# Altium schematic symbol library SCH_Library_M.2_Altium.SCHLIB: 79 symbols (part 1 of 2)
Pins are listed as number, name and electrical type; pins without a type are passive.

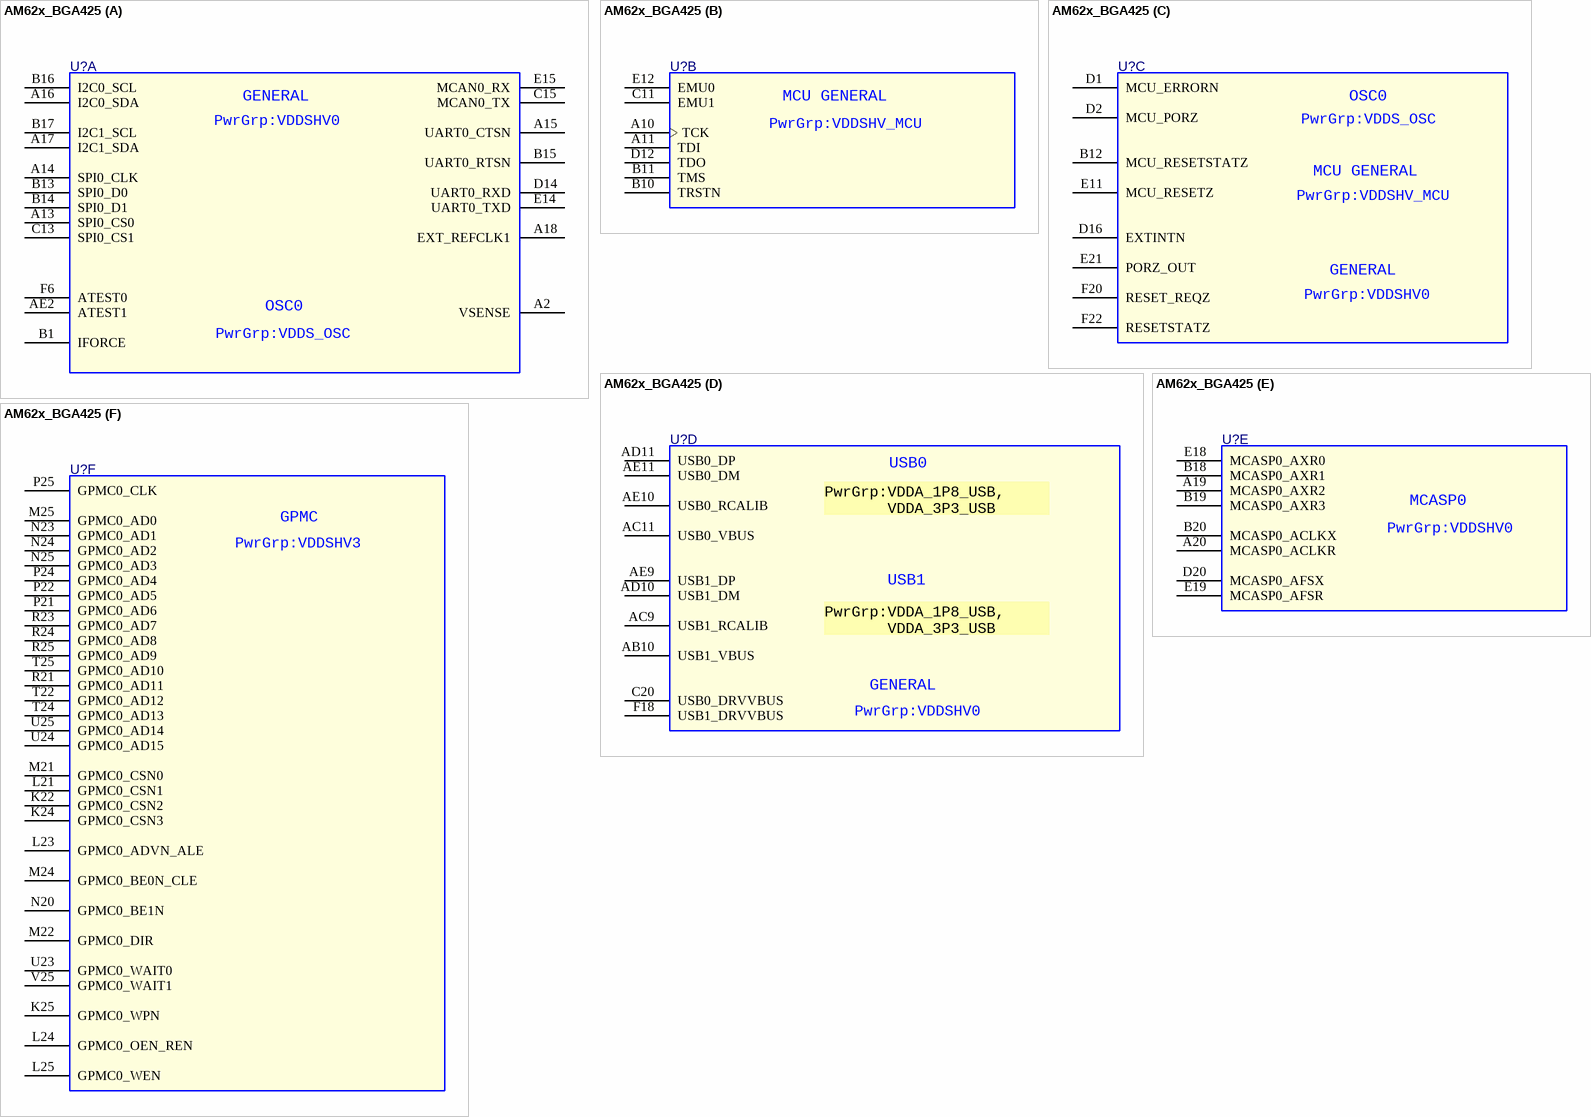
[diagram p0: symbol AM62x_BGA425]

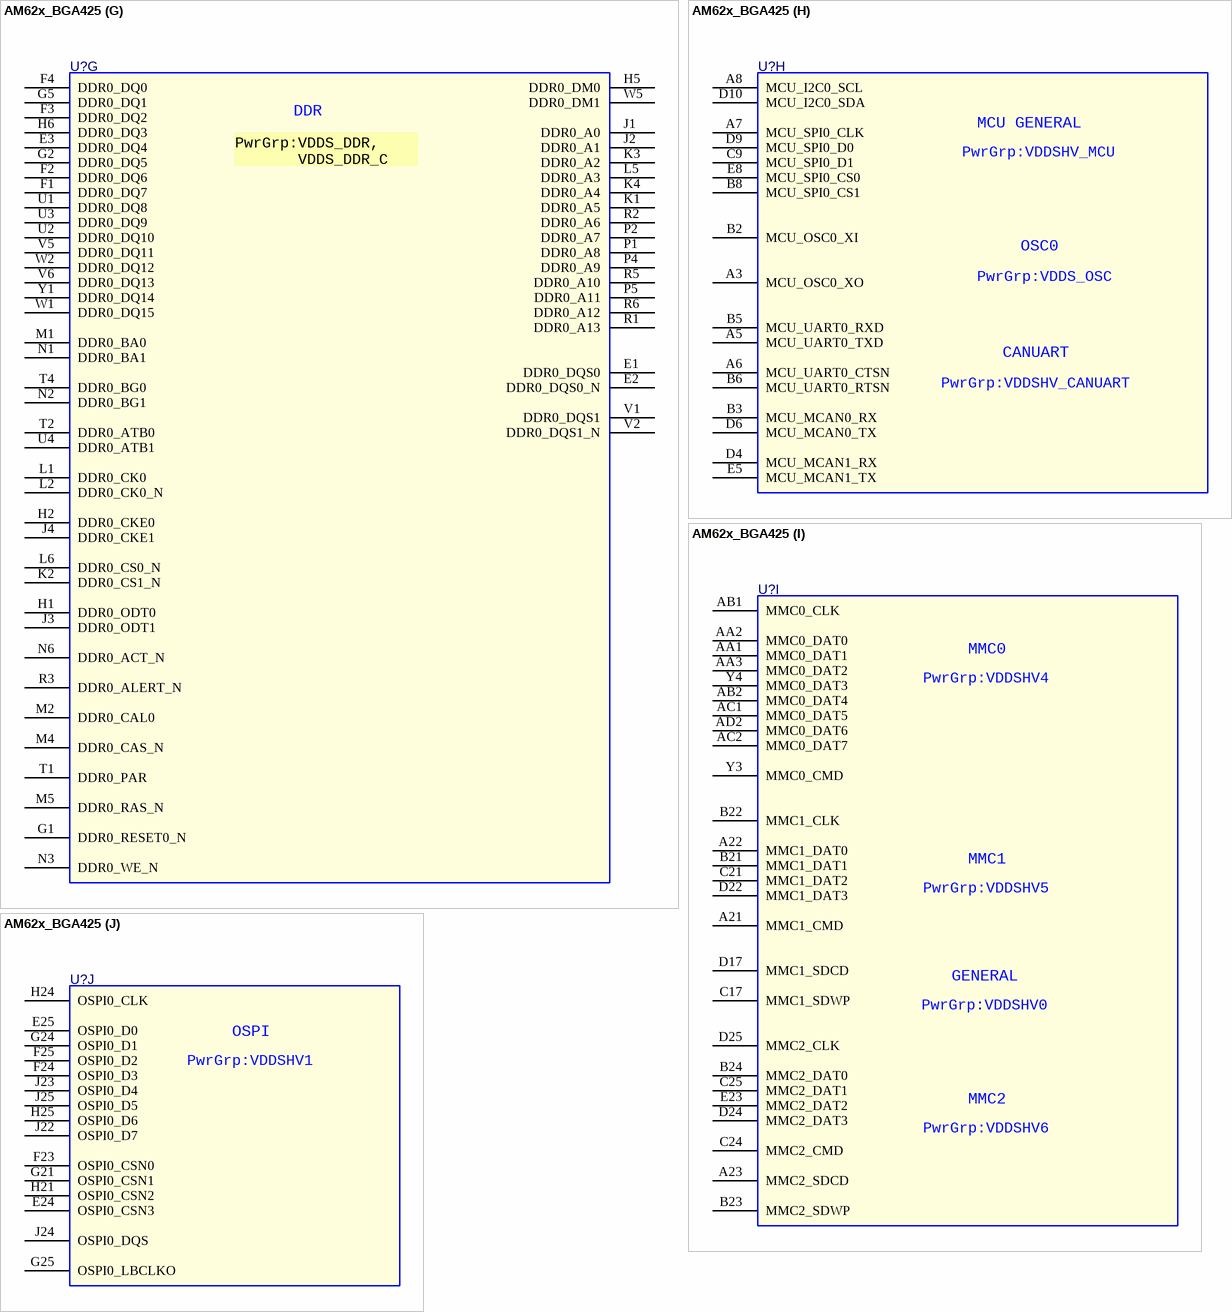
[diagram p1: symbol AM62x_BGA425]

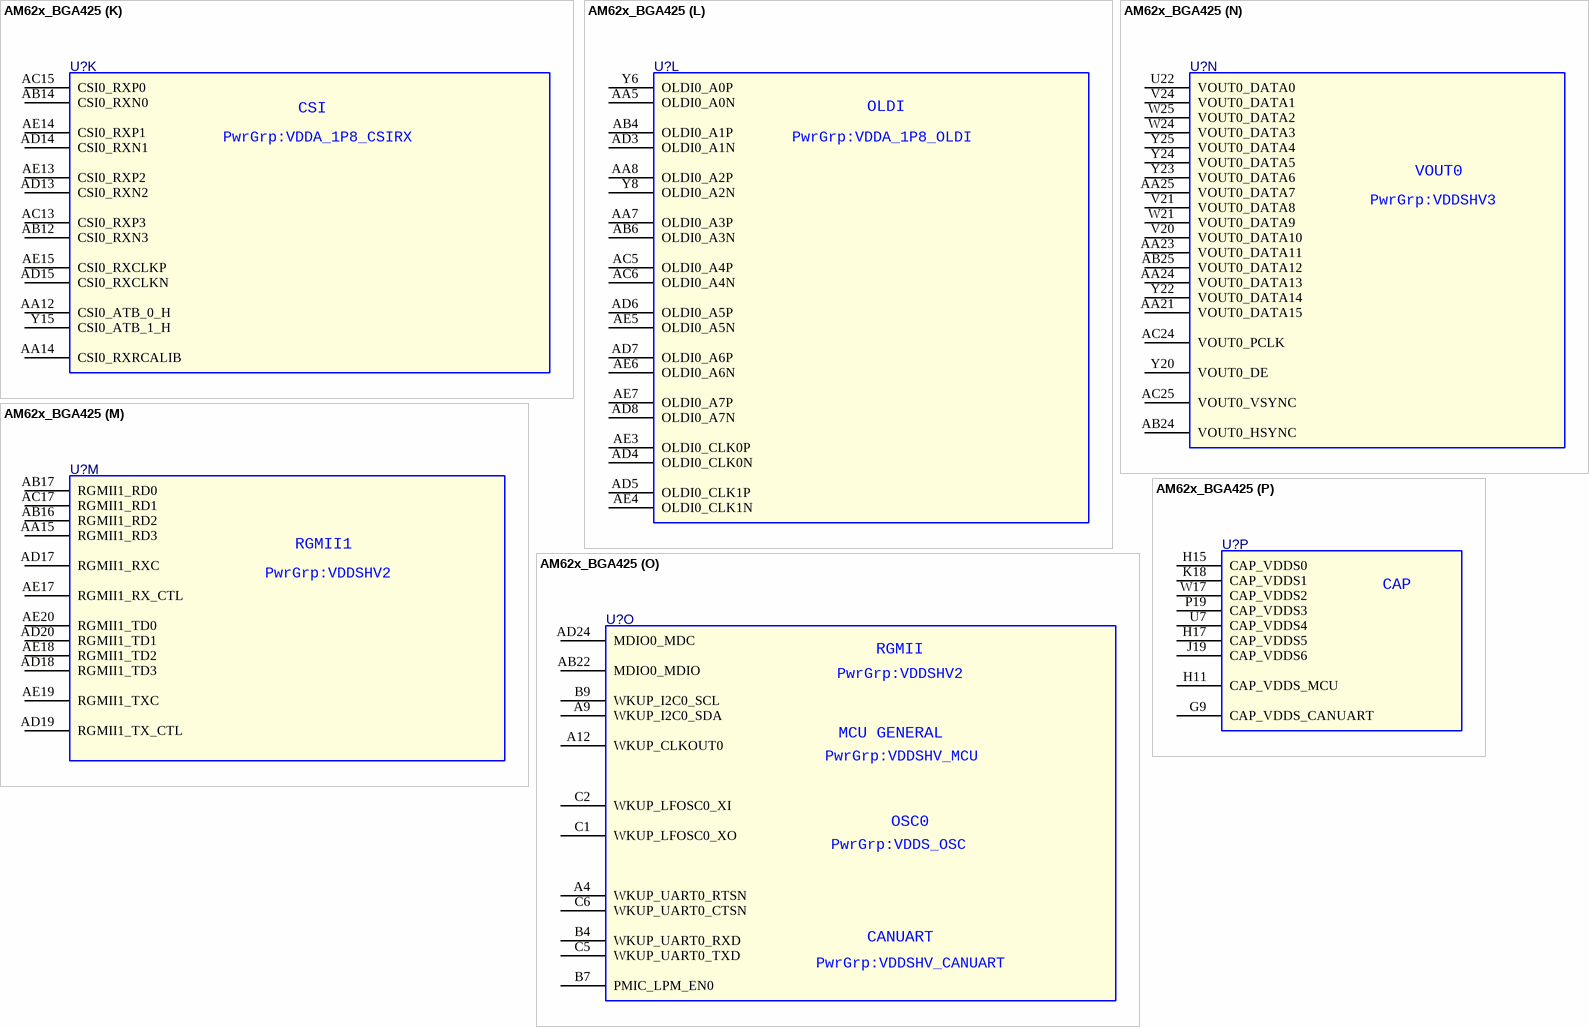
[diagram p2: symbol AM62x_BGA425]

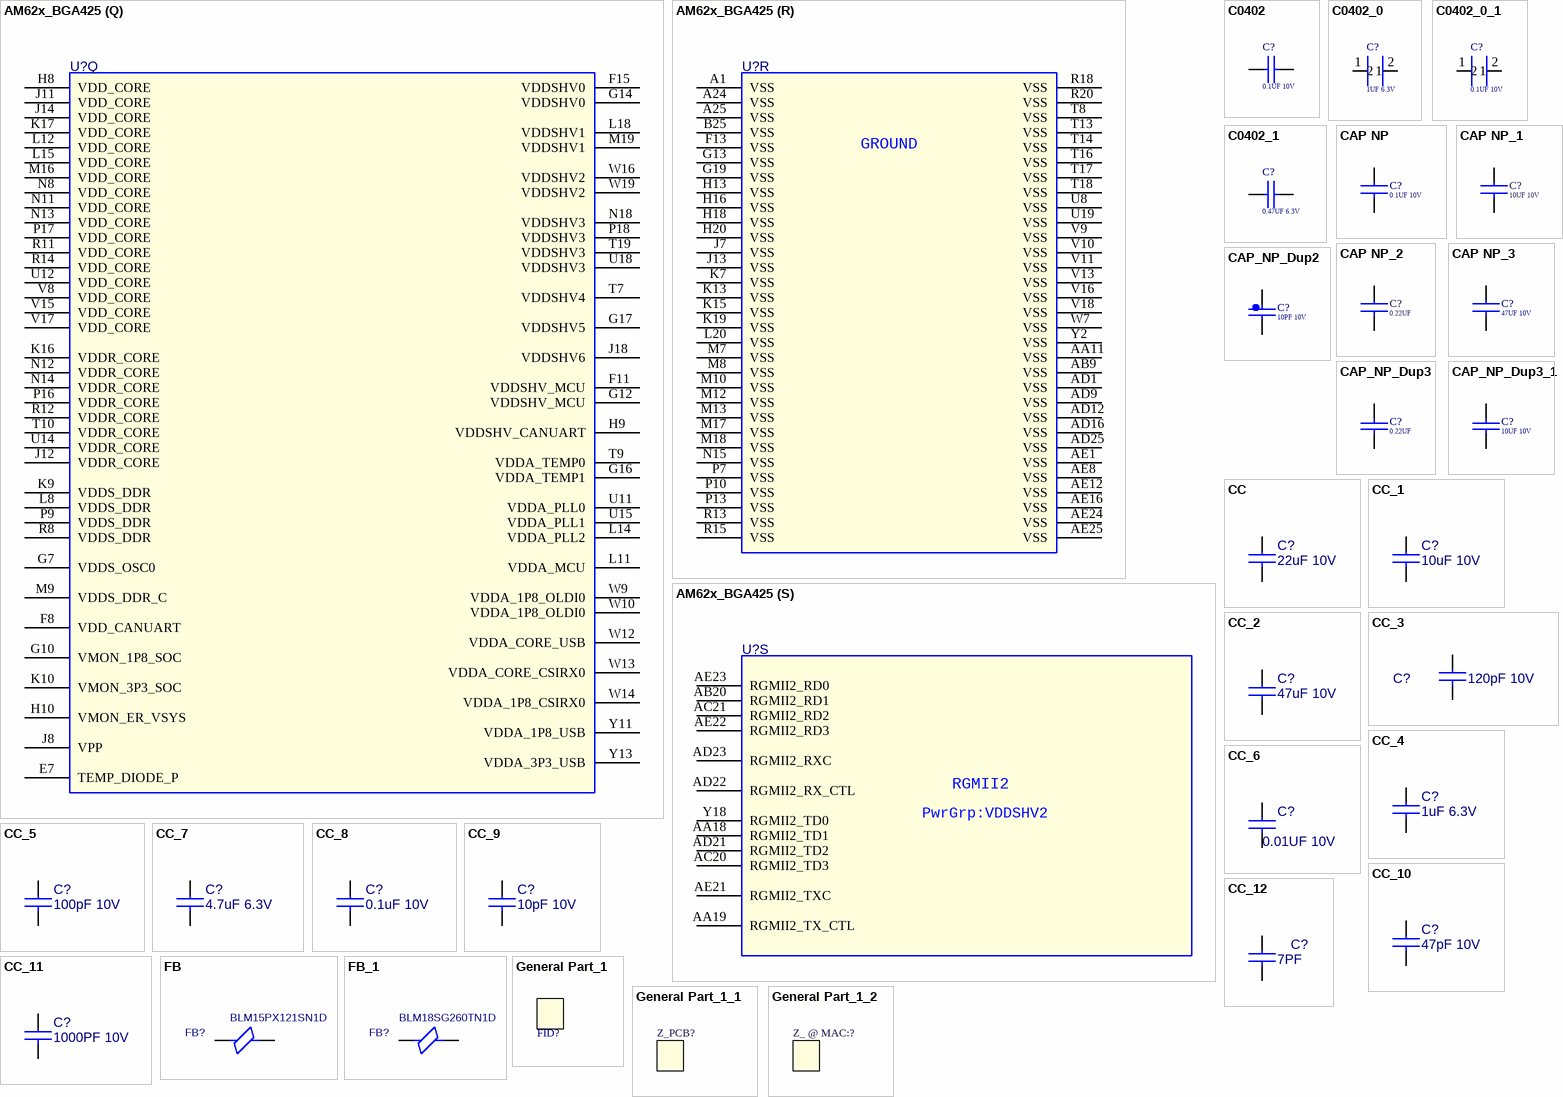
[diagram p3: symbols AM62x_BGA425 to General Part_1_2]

## AM62x_BGA425
designator U?  (value not drawn)
4 Core, 64-Bit 1.4GHz 425-FCC; 01. ASET1 UI1: ------------; 01. Set1/BD#: BD3429; 02. Set1/MF1: Texas Instruments; 03. Set1/PN1: AM6254ATCGHAALW; 09. Z Lay/FP: bga425_0d5_13x13mm
footprint bga425_0d5_13x13mm
part A pins: A2 VSENSE, A13 SPI0_CS0, A14 SPI0_CLK, A15 UART0_CTSN, A16 I2C0_SDA, A17 I2C1_SDA, A18 EXT_REFCLK1, AE2 ATEST1, B1 IFORCE, B13 SPI0_D0, B14 SPI0_D1, B15 UART0_RTSN, B16 I2C0_SCL, B17 I2C1_SCL, C13 SPI0_CS1, C15 MCAN0_TX, D14 UART0_RXD, E14 UART0_TXD, E15 MCAN0_RX, F6 ATEST0
part B pins: A10 TCK, A11 TDI, B10 TRSTN, B11 TMS, C11 EMU1, D12 TDO, E12 EMU0
part C pins: B12 MCU_RESETSTATZ, D1 MCU_ERRORN, D2 MCU_PORZ, D16 EXTINTN, E11 MCU_RESETZ, E21 PORZ_OUT, F20 RESET_REQZ, F22 RESETSTATZ
part D pins: AB10 USB1_VBUS, AC9 USB1_RCALIB, AC11 USB0_VBUS, AD10 USB1_DM, AD11 USB0_DP, AE9 USB1_DP, AE10 USB0_RCALIB, AE11 USB0_DM, C20 USB0_DRVVBUS, F18 USB1_DRVVBUS
part E pins: A19 MCASP0_AXR2, A20 MCASP0_ACLKR, B18 MCASP0_AXR1, B19 MCASP0_AXR3, B20 MCASP0_ACLKX, D20 MCASP0_AFSX, E18 MCASP0_AXR0, E19 MCASP0_AFSR
part F pins: K22 GPMC0_CSN2, K24 GPMC0_CSN3, K25 GPMC0_WPN, L21 GPMC0_CSN1, L23 GPMC0_ADVN_ALE, L24 GPMC0_OEN_REN, L25 GPMC0_WEN, M21 GPMC0_CSN0, M22 GPMC0_DIR, M24 GPMC0_BE0N_CLE, M25 GPMC0_AD0, N20 GPMC0_BE1N, N23 GPMC0_AD1, N24 GPMC0_AD2, N25 GPMC0_AD3, P21 GPMC0_AD6, P22 GPMC0_AD5, P24 GPMC0_AD4, P25 GPMC0_CLK, R21 GPMC0_AD11, R23 GPMC0_AD7, R24 GPMC0_AD8, R25 GPMC0_AD9, T22 GPMC0_AD12, T24 GPMC0_AD13, T25 GPMC0_AD10, U23 GPMC0_WAIT0, U24 GPMC0_AD15, U25 GPMC0_AD14, V25 GPMC0_WAIT1
part G pins: E1 DDR0_DQS0, E2 DDR0_DQS0_N, E3 DDR0_DQ4, F1 DDR0_DQ7, F2 DDR0_DQ6, F3 DDR0_DQ2, F4 DDR0_DQ0, G1 DDR0_RESET0_N, G2 DDR0_DQ5, G5 DDR0_DQ1, H1 DDR0_ODT0, H2 DDR0_CKE0, H5 DDR0_DM0, H6 DDR0_DQ3, J1 DDR0_A0, J2 DDR0_A1, J3 DDR0_ODT1, J4 DDR0_CKE1, K1 DDR0_A5, K2 DDR0_CS1_N, K3 DDR0_A2, K4 DDR0_A4, L1 DDR0_CK0, L2 DDR0_CK0_N, L5 DDR0_A3, L6 DDR0_CS0_N, M1 DDR0_BA0, M2 DDR0_CAL0, M4 DDR0_CAS_N, M5 DDR0_RAS_N, N1 DDR0_BA1, N2 DDR0_BG1, N3 DDR0_WE_N, N6 DDR0_ACT_N, P1 DDR0_A8, P2 DDR0_A7, P4 DDR0_A9, P5 DDR0_A11, R1 DDR0_A13, R2 DDR0_A6, R3 DDR0_ALERT_N, R5 DDR0_A10, R6 DDR0_A12, T1 DDR0_PAR, T2 DDR0_ATB0, T4 DDR0_BG0, U1 DDR0_DQ8, U2 DDR0_DQ10, U3 DDR0_DQ9, U4 DDR0_ATB1, V1 DDR0_DQS1, V2 DDR0_DQS1_N, V5 DDR0_DQ11, V6 DDR0_DQ13, W1 DDR0_DQ15, W2 DDR0_DQ12, W5 DDR0_DM1, Y1 DDR0_DQ14
part H pins: A3 MCU_OSC0_XO, A5 MCU_UART0_TXD, A6 MCU_UART0_CTSN, A7 MCU_SPI0_CLK, A8 MCU_I2C0_SCL, B2 MCU_OSC0_XI, B3 MCU_MCAN0_RX, B5 MCU_UART0_RXD, B6 MCU_UART0_RTSN, B8 MCU_SPI0_CS1, C9 MCU_SPI0_D1, D4 MCU_MCAN1_RX, D6 MCU_MCAN0_TX, D9 MCU_SPI0_D0, D10 MCU_I2C0_SDA, E5 MCU_MCAN1_TX, E8 MCU_SPI0_CS0
part I pins: A21 MMC1_CMD, A22 MMC1_DAT0, A23 MMC2_SDCD, AA1 MMC0_DAT1, AA2 MMC0_DAT0, AA3 MMC0_DAT2, AB1 MMC0_CLK, AB2 MMC0_DAT4, AC1 MMC0_DAT5, AC2 MMC0_DAT7, AD2 MMC0_DAT6, B21 MMC1_DAT1, B22 MMC1_CLK, B23 MMC2_SDWP, B24 MMC2_DAT0, C17 MMC1_SDWP, C21 MMC1_DAT2, C24 MMC2_CMD, C25 MMC2_DAT1, D17 MMC1_SDCD, D22 MMC1_DAT3, D24 MMC2_DAT3, D25 MMC2_CLK, E23 MMC2_DAT2, Y3 MMC0_CMD, Y4 MMC0_DAT3
part J pins: E24 OSPI0_CSN3, E25 OSPI0_D0, F23 OSPI0_CSN0, F24 OSPI0_D3, F25 OSPI0_D2, G21 OSPI0_CSN1, G24 OSPI0_D1, G25 OSPI0_LBCLKO, H21 OSPI0_CSN2, H24 OSPI0_CLK, H25 OSPI0_D6, J22 OSPI0_D7, J23 OSPI0_D4, J24 OSPI0_DQS, J25 OSPI0_D5
part K pins: AA12 CSI0_ATB_0_H, AA14 CSI0_RXRCALIB, AB12 CSI0_RXN3, AB14 CSI0_RXN0, AC13 CSI0_RXP3, AC15 CSI0_RXP0, AD13 CSI0_RXN2, AD14 CSI0_RXN1, AD15 CSI0_RXCLKN, AE13 CSI0_RXP2, AE14 CSI0_RXP1, AE15 CSI0_RXCLKP, Y15 CSI0_ATB_1_H
part L pins: AA5 OLDI0_A0N, AA7 OLDI0_A3P, AA8 OLDI0_A2P, AB4 OLDI0_A1P, AB6 OLDI0_A3N, AC5 OLDI0_A4P, AC6 OLDI0_A4N, AD3 OLDI0_A1N, AD4 OLDI0_CLK0N, AD5 OLDI0_CLK1P, AD6 OLDI0_A5P, AD7 OLDI0_A6P, AD8 OLDI0_A7N, AE3 OLDI0_CLK0P, AE4 OLDI0_CLK1N, AE5 OLDI0_A5N, AE6 OLDI0_A6N, AE7 OLDI0_A7P, Y6 OLDI0_A0P, Y8 OLDI0_A2N
part M pins: AA15 RGMII1_RD3, AB16 RGMII1_RD2, AB17 RGMII1_RD0, AC17 RGMII1_RD1, AD17 RGMII1_RXC, AD18 RGMII1_TD3, AD19 RGMII1_TX_CTL, AD20 RGMII1_TD1, AE17 RGMII1_RX_CTL, AE18 RGMII1_TD2, AE19 RGMII1_TXC, AE20 RGMII1_TD0
part N pins: AA21 VOUT0_DATA15, AA23 VOUT0_DATA11, AA24 VOUT0_DATA13, AA25 VOUT0_DATA7, AB24 VOUT0_HSYNC, AB25 VOUT0_DATA12, AC24 VOUT0_PCLK, AC25 VOUT0_VSYNC, U22 VOUT0_DATA0, V20 VOUT0_DATA10, V21 VOUT0_DATA8, V24 VOUT0_DATA1, W21 VOUT0_DATA9, W24 VOUT0_DATA3, W25 VOUT0_DATA2, Y20 VOUT0_DE, Y22 VOUT0_DATA14, Y23 VOUT0_DATA6, Y24 VOUT0_DATA5, Y25 VOUT0_DATA4
part O pins: A4 WKUP_UART0_RTSN, A9 WKUP_I2C0_SDA, A12 WKUP_CLKOUT0, AB22 MDIO0_MDIO, AD24 MDIO0_MDC, B4 WKUP_UART0_RXD, B7 PMIC_LPM_EN0, B9 WKUP_I2C0_SCL, C1 WKUP_LFOSC0_XO, C2 WKUP_LFOSC0_XI, C5 WKUP_UART0_TXD, C6 WKUP_UART0_CTSN
part P pins: G9 CAP_VDDS_CANUART, H11 CAP_VDDS_MCU, H15 CAP_VDDS0, H17 CAP_VDDS5, J19 CAP_VDDS6, K18 CAP_VDDS1, P19 CAP_VDDS3, U7 CAP_VDDS4, W17 CAP_VDDS2
part Q pins: E7 TEMP_DIODE_P, F8 VDD_CANUART (power), F11 VDDSHV_MCU (power), F15 VDDSHV0 (power), G7 VDDS_OSC0 (power), G10 VMON_1P8_SOC (power), G12 VDDSHV_MCU (power), G14 VDDSHV0 (power), G16 VDDA_TEMP1 (power), G17 VDDSHV5 (power), H8 VDD_CORE (power), H9 VDDSHV_CANUART (power), H10 VMON_ER_VSYS (power), J8 VPP (power), J11 VDD_CORE (power), J12 VDDR_CORE (power), J14 VDD_CORE (power), J18 VDDSHV6 (power), K9 VDDS_DDR (power), K10 VMON_3P3_SOC (power), K16 VDDR_CORE (power), K17 VDD_CORE (power), L8 VDDS_DDR (power), L11 VDDA_MCU (power), L12 VDD_CORE (power), L14 VDDA_PLL2 (power), L15 VDD_CORE (power), L18 VDDSHV1 (power), M9 VDDS_DDR_C (power), M16 VDD_CORE (power), M19 VDDSHV1 (power), N8 VDD_CORE (power), N11 VDD_CORE (power), N12 VDDR_CORE (power), N13 VDD_CORE (power), N14 VDDR_CORE (power), N18 VDDSHV3 (power), P9 VDDS_DDR (power), P16 VDDR_CORE (power), P17 VDD_CORE (power), P18 VDDSHV3 (power), R8 VDDS_DDR (power), R11 VDD_CORE (power), R12 VDDR_CORE (power), R14 VDD_CORE (power), T7 VDDSHV4 (power), T9 VDDA_TEMP0 (power), T10 VDDR_CORE (power), T19 VDDSHV3 (power), U11 VDDA_PLL0 (power), U12 VDD_CORE (power), U14 VDDR_CORE (power), U15 VDDA_PLL1 (power), U18 VDDSHV3 (power), V8 VDD_CORE (power), V15 VDD_CORE (power), V17 VDD_CORE (power), W9 VDDA_1P8_OLDI0 (power), W10 VDDA_1P8_OLDI0 (power), W12 VDDA_CORE_USB (power), W13 VDDA_CORE_CSIRX0 (power), W14 VDDA_1P8_CSIRX0 (power), W16 VDDSHV2 (power), W19 VDDSHV2 (power), Y11 VDDA_1P8_USB (power), Y13 VDDA_3P3_USB (power)
part R pins: A1 VSS (power), A24 VSS (power), A25 VSS (power), AA11 VSS (power), AB9 VSS (power), AD1 VSS (power), AD9 VSS (power), AD12 VSS (power), AD16 VSS (power), AD25 VSS (power), AE1 VSS (power), AE8 VSS (power), AE12 VSS (power), AE16 VSS (power), AE24 VSS (power), AE25 VSS (power), B25 VSS (power), F13 VSS (power), G13 VSS (power), G19 VSS (power), H13 VSS (power), H16 VSS (power), H18 VSS (power), H20 VSS (power), J7 VSS (power), J13 VSS (power), K7 VSS (power), K13 VSS (power), K15 VSS (power), K19 VSS (power), L20 VSS (power), M7 VSS (power), M8 VSS (power), M10 VSS (power), M12 VSS (power), M13 VSS (power), M17 VSS (power), M18 VSS (power), N15 VSS (power), P7 VSS (power), P10 VSS (power), P13 VSS (power), R13 VSS (power), R15 VSS (power), R18 VSS (power), R20 VSS (power), T8 VSS (power), T13 VSS (power), T14 VSS (power), T16 VSS (power), T17 VSS (power), T18 VSS (power), U8 VSS (power), U19 VSS (power), V9 VSS (power), V10 VSS (power), V11 VSS (power), V13 VSS (power), V16 VSS (power), V18 VSS (power), W7 VSS (power), Y2 VSS (power)
part S pins: AA18 RGMII2_TD1, AA19 RGMII2_TX_CTL, AB20 RGMII2_RD1, AC20 RGMII2_TD3, AC21 RGMII2_RD2, AD21 RGMII2_TD2, AD22 RGMII2_RX_CTL, AD23 RGMII2_RXC, AE21 RGMII2_TXC, AE22 RGMII2_RD3, AE23 RGMII2_RD0, Y18 RGMII2_TD0

## C0402
designator C?, comment 0.1UF 10V
0.1UF 10V X5R 01005; 01. ASET1 UI1: ------------; 01. Set1/BD#: BD3313; 02. Set1/MF1: Murata Electronics; 03. Set1/PN1: GRM022R61A104KE01L; 09. Z Lay/FP: CAPC0402L_1005
footprint CAPC1005L_0402
footprint CAPC0603L_0201
footprint CAP01005_0402
footprint CAPC0402L_1005
pins: 1, 2

## C0402_0
designator C?, comment 1UF 6.3V
1UF 10V X5R 0201 20%; 01. ASET1 UI1: ------------; 01. Set1/BD#: BD2160; 02. Set1/MF1: Samsung; 03. Set1/PN1: CL03A105KP3NSNC; 09. Z Lay/FP: CAPC0603L_0201
footprint CAPC1005L
footprint CC0603
footprint CAPC0603L_0201
footprint CAPC0603L_0201 - NXP
pins: 1, 2

## C0402_0_1
designator C?, comment 0.1UF 10V
0.1UF 10V X5R 01005; 01. ASET1 UI1: ------------; 01. Set1/BD#: BD3313; 02. Set1/MF1: Murata Electronics; 03. Set1/PN1: GRM022R61A104KE01L; 09. Z Lay/FP: CAPC0402L_1005
footprint CAPC1005L
footprint CC0603
footprint CAPC0603L_0201
footprint CAPC0402L_1005
pins: 1, 2

## C0402_1
designator C?, comment 0.47UF 6.3V
0.47UF 6.3V X5R 01005; 01. ASET1 UI1: ------------; 01. Set1/BD#: BD3325; 02. Set1/MF1: Murata Electronics; 03. Set1/PN1: GRM022R60J474ME15L; 09. Z Lay/FP: CAPC0402L_1005
footprint CAPC1005L_0402
footprint CAPC0603L_0201
footprint CAPC0402L_1005
pins: 1, 2

## CAP NP
designator C?, comment 0.1UF 10V
0.1UF 10V X5R 01005; 01. ASET1 UI1: ------------; 01. Set1/BD#: BD3313; 02. Set1/MF1: Murata Electronics; 03. Set1/PN1: GRM022R61A104KE01L; 09. Z Lay/FP: CAPC0402L_1005
footprint CAPC0603L_0201
footprint CAP01005_0402
footprint CAPC0402L_1005
pins: 1, 2

## CAP NP_1
designator C?, comment 10UF 10V
10UF 10V X5R 0402; 01. ASET1 UI1: ------------; 01. Set1/BD#: BD3317; 02. Set1/MF1: Samsung; 03. Set1/PN1: CL05A106MP5NUNC; 09. Z Lay/FP: CAPC1005L_0402
footprint CAPC1005L_0402
footprint CAPC1005L_0402_OSM
pins: 1, 2

## CAP NP_2
designator C?, comment 0.22UF
0.22UF 6.3V X5R 01005; 01. ASET1 UI1: ------------; 01. Set1/BD#: BD3315; 02. Set1/MF1: Murata Electronics; 03. Set1/PN1: GRM022R60J224KE14L; 09. Z Lay/FP: CAPC0402L_1005
footprint CAPC0603L_0201
footprint CAPC0402L_1005
pins: 1, 2

## CAP NP_3
designator C?, comment 47UF 10V
47uF 10V X5R  0805; 01. ASET1 UI1: ------------; 01. Set1/BD#: BD1465; 02. Set1/MF1: TDK; 03. Set1/PN1: C2012X5R1A476M125AC; 09. Z Lay/FP: CAPC2012L_0805
footprint CAPC2012L_0805
footprint CAPC2012L_0805_OSM
pins: 1, 2

## CAP_NP_Dup2
designator C?, comment 10PF 10V
10PF 16V C0G/NPO 01005; 01. ASET1 UI1: ------------; 01. Set1/BD#: BD3322; 02. Set1/MF1: Yageo; 03. Set1/PN1: CC0100JRNPO7BN100; 09. Z Lay/FP: CAPC0402L_1005
footprint CAPC1005L
footprint CAPC0603L_0201
footprint CAPC0402L_1005
pins: 1, 2

## CAP_NP_Dup3
designator C?, comment 0.22UF
0.22UF 6.3V X5R 01005; 01. ASET1 UI1: ------------; 01. Set1/BD#: BD3315; 02. Set1/MF1: Murata Electronics; 03. Set1/PN1: GRM022R60J224KE14L; 09. Z Lay/FP: CAPC0402L_1005
footprint CAPC0603L_0201
footprint CAPC0402L_1005
pins: 1, 2

## CAP_NP_Dup3_1
designator C?, comment 10UF 10V
10UF 10V X5R 0402; 01. ASET1 UI1: ------------; 01. Set1/BD#: BD3317; 02. Set1/MF1: Samsung; 03. Set1/PN1: CL05A106MP5NUNC; 09. Z Lay/FP: CAPC1005L_0402
footprint CAPC0603L_0201
footprint CAPC1005L_0402
pins: 1, 2

## CC
designator C?, comment 22uF 10V
22UF 10V X5R 0402; 01. ASET1 UI1: ------------; 01. Set1/BD#: BD3319; 02. Set1/MF1: Murata Electronics; 03. Set1/PN1: GRM158R61A226ME15D; 09. Z Lay/FP: CAPC1005L_0402
footprint C0402
footprint CAPC1005L_0402
pins: 1, 2
1 alternate drawing of the same symbol

## CC_1
designator C?, comment 10uF 10V
10UF 10V X5R 0402; 01. ASET1 UI1: ------------; 01. Set1/BD#: BD3317; 02. Set1/MF1: Samsung; 03. Set1/PN1: CL05A106MP5NUNC; 09. Z Lay/FP: CAPC1005L_0402
footprint C0603
footprint CAPC1005L_0402
pins: 1, 2
1 alternate drawing of the same symbol

## CC_2
designator C?, comment 47uF 10V
47uF 10V X5R  0805; 01. ASET1 UI1: ------------; 01. Set1/BD#: BD1465; 02. Set1/MF1: TDK; 03. Set1/PN1: C2012X5R1A476M125AC; 09. Z Lay/FP: CAPC2012L_0805
footprint C0805
footprint CAPC2012L_0805
footprint CAPC2012L_0805_OSM
pins: 1, 2
1 alternate drawing of the same symbol

## CC_3
designator C?, comment 120pF 10V
120PF 10V X7R 01005; 01. ASET1 UI1: ------------; 01. Set1/BD#: BD3324; 02. Set1/MF1: Murata Electronics; 03. Set1/PN1: GRM022R71A121KA01L; 09. Z Lay/FP: CAPC0402L_1005
footprint C0402
footprint CAPC0402L_1005
pins: 1, 2
1 alternate drawing of the same symbol

## CC_4
designator C?, comment 1uF 6.3V
1UF 10V X5R 0201 20%; 01. ASET1 UI1: ------------; 01. Set1/BD#: BD2160; 02. Set1/MF1: Samsung; 03. Set1/PN1: CL03A105KP3NSNC; 09. Z Lay/FP: CAPC0603L_0201
footprint C0201
footprint CAPC0603L_0201
pins: 1, 2
1 alternate drawing of the same symbol

## CC_5
designator C?, comment 100pF 10V
100PF 25V C0G/NP0 01005; 01. ASET1 UI1: ------------; 01. Set1/BD#: BD3314; 02. Set1/MF1: Murata Electronics; 03. Set1/PN1: GRM0225C1E101JA02L; 09. Z Lay/FP: CAPC0402L_1005
footprint C0201
footprint CAP01005_0402
footprint CAPC0402L_1005
pins: 1, 2
1 alternate drawing of the same symbol

## CC_6
designator C?, comment 0.01UF 10V
0.01UF 10V X5R 01005; 01. ASET1 UI1: ------------; 01. Set1/BD#: BD3320; 02. Set1/MF1: Murata Electronics; 03. Set1/PN1: GRM022R61A103KE19L; 09. Z Lay/FP: CAPC0402L_1005
footprint C0201
footprint CAPC0402L_1005
pins: 1, 2
1 alternate drawing of the same symbol

## CC_7
designator C?, comment 4.7uF 6.3V
4.7UF 6.3V X5R 0201; 01. ASET1 UI1: ------------; 01. Set1/BD#: BD2821; 02. Set1/MF1: Murata Electronics; 03. Set1/PN1: GRM035R60J475ME15D; 09. Z Lay/FP: CAPC0603L_0201
footprint C0402
footprint CAPC0603L_0201
pins: 1, 2
1 alternate drawing of the same symbol

## CC_8
designator C?, comment 0.1uF 10V
0.1UF 10V X5R 01005; 01. ASET1 UI1: ------------; 01. Set1/BD#: BD3313; 02. Set1/MF1: Murata Electronics; 03. Set1/PN1: GRM022R61A104KE01L; 09. Z Lay/FP: CAPC0402L_1005
footprint C0201
footprint CAP01005_0402
footprint CAPC0402L_1005
pins: 1, 2
1 alternate drawing of the same symbol

## CC_9
designator C?, comment 10pF 10V
10PF 16V C0G/NPO 01005; 01. ASET1 UI1: ------------; 01. Set1/BD#: BD3322; 02. Set1/MF1: Yageo; 03. Set1/PN1: CC0100JRNPO7BN100; 09. Z Lay/FP: CAPC0402L_1005
footprint C0201
footprint CAPC0402L_1005
pins: 1, 2
1 alternate drawing of the same symbol

## CC_10
designator C?, comment 47pF 10V
47PF 25V C0G/NP0 01005; 01. ASET1 UI1: ------------; 01. Set1/BD#: BD3321; 02. Set1/MF1: Murata Electronics; 03. Set1/PN1: GRM0225C1E470JA02L; 09. Z Lay/FP: CAPC0402L_1005
footprint C0201
footprint CAPC0402L_1005
pins: 1, 2
1 alternate drawing of the same symbol

## CC_11
designator C?, comment 1000PF 10V
1000PF 10V X7R 01005; 01. ASET1 UI1: ------------; 01. Set1/BD#: BD3318; 02. Set1/MF1: Murata Electronics; 03. Set1/PN1: GRM022R71A102KA12L; 09. Z Lay/FP: CAPC0402L_1005
footprint C0201
footprint CAPC0402L_1005
pins: 1, 2
1 alternate drawing of the same symbol

## CC_12
designator C?, comment 7PF
7PF 25V C0G/NP0 01005; 01. ASET1 UI1: ------------; 01. Set1/BD#: BD3419; 02. Set1/MF1: Murata Electronics; 03. Set1/PN1: GRM0225C1E7R0WA03L; 09. Z Lay/FP: CAPC0402L_1005
footprint C0402
footprint CAPC0402L_1005
pins: 1, 2
1 alternate drawing of the same symbol

## FB
designator FB?, comment BLM15PX121SN1D
FERRITE BEAD 120 OHM 0402 1LN; 01. ASET1 UI1: ------------; 01. Set1/BD#: BD3326; 02. Set1/MF1: Murata Electronics
footprint L0402
footprint BLM15PX121SN1D
pins: 1, 2

## FB_1
designator FB?, comment BLM18SG260TN1D
FERRITE BEAD 26 OHM 0603 1LN; 01. ASET1 UI1: ------------; 01. Set1/BD#: BD3328; 02. Set1/MF1: Murata Electronics
footprint L0402
footprint BLM15PX121SN1D
footprint ????
footprint BLM18SG260TN1D
pins: 1, 2

## General Part_1
designator FID?, comment FIDUCIAL  (value not drawn)  (no BOM)
CPU HEAT SINK; 01. ASET1 UI1: ------------; 09. Z Lay/FP: FIDUCIAL_OSM
footprint FIDUCIAL10-20
footprint FIDUCIAL_OSM

## General Part_1_1
designator Z_PCB?  (mechanical)
Printed Circuit Board; 01. ASET1 UI1: ------------; 01. Set1/BD#: PCB_EZOMI-625_REV3-0

## General Part_1_2
designator Z_ @ MAC:?  (mechanical)
MAC address label; 01. ASET1 UI1: ------------; 01. Set1/BD#: BD_MAC_Label_SM; 02. Set1/MF1: Boundary Devices

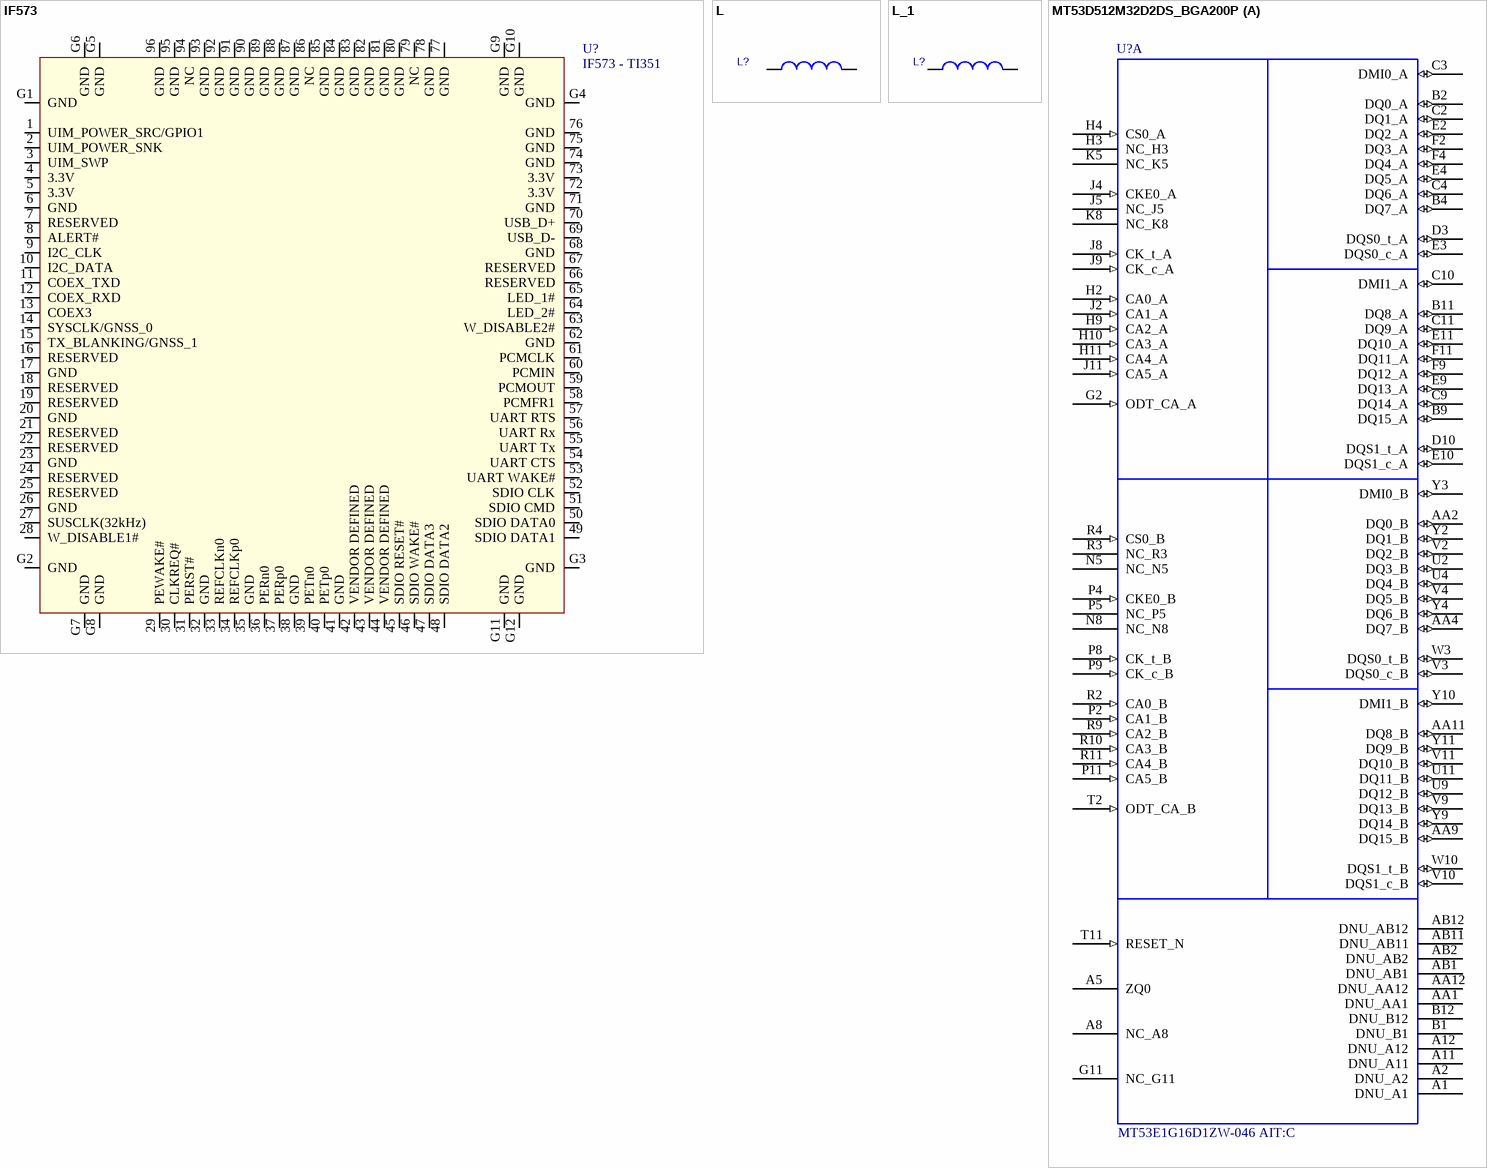
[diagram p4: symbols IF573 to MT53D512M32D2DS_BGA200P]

## IF573
designator U?, comment IF573 - TI351
Multiprotocol Modules Module,; 01. Set1/BD#: 453-00117; 01. ASET1 UI1: ------------; 02. Set1/MF1: Ezurio; 03. Set1/PN1: 453-00117C
footprint MT921_M.2_1420
footprint IF573
pins: 1 UIM_POWER_SRC/GPIO1, 2 UIM_POWER_SNK, 3 UIM_SWP, 4 3.3V, 5 3.3V, 6 GND, 7 RESERVED, 8 ALERT#, 9 I2C_CLK, 10 I2C_DATA, 11 COEX_TXD, 12 COEX_RXD, 13 COEX3, 14 SYSCLK/GNSS_0, 15 TX_BLANKING/GNSS_1, 16 RESERVED, 17 GND, 18 RESERVED, 19 RESERVED, 20 GND, 21 RESERVED, 22 RESERVED, 23 GND, 24 RESERVED, 25 RESERVED, 26 GND, 27 SUSCLK(32kHz), 28 W_DISABLE1#, 29 PEWAKE#, 30 CLKREQ#, 31 PERST#, 32 GND, 33 REFCLKn0, 34 REFCLKp0, 35 GND, 36 PERn0, 37 PERp0, 38 GND, 39 PETn0, 40 PETp0, 41 GND, 42 VENDOR DEFINED, 43 VENDOR DEFINED, 44 VENDOR DEFINED, 45 SDIO RESET#, 46 SDIO WAKE#, 47 SDIO DATA3, 48 SDIO DATA2, 49 SDIO DATA1, 50 SDIO DATA0, 51 SDIO CMD, 52 SDIO CLK, 53 UART WAKE#, 54 UART CTS, 55 UART Tx, 56 UART Rx, 57 UART RTS, 58 PCMFR1, 59 PCMOUT, 60 PCMIN, 61 PCMCLK, 62 GND, 63 W_DISABLE2#, 64 LED_2#, 65 LED_1#, 66 RESERVED, 67 RESERVED, 68 GND, 69 USB_D-, 70 USB_D+, 71 GND, 72 3.3V, 73 3.3V, 74 GND, 75 GND, 76 GND, 77 GND, 78 GND, 79 NC, 80 GND, 81 GND, 82 GND, 83 GND, 84 GND, 85 GND, 86 NC, 87 GND, 88 GND, 89 GND, 90 GND, 91 GND, 92 GND, 93 GND, 94 NC, 95 GND, 96 GND, G1 GND, G2 GND, G3 GND, G4 GND, G5 GND, G6 GND, G7 GND, G8 GND, G9 GND, G10 GND, G11 GND, G12 GND

## L
designator L?, comment AOTA-B252010SR47MT  (value not drawn)
FIXED IND 0.47UH 5.7A 20MOHM SMD; 01. ASET1 UI1: ------------; 01. Set1/BD#: BD3347; 02. Set1/MF1: Abracon LLC
footprint L1008
footprint AOTA-1008
pins: 1, 2
1 alternate drawing of the same symbol

## L_1
designator L?, comment AOTA-B252010SR33MT  (value not drawn)
FIXED IND 0.33UH 5.0A 16MOHM SMD; 01. ASET1 UI1: ------------; 01. Set1/BD#: BD3331; 02. Set1/MF1: Abracon LLC
footprint L1008
footprint AOTA-1008
pins: 1, 2
1 alternate drawing of the same symbol

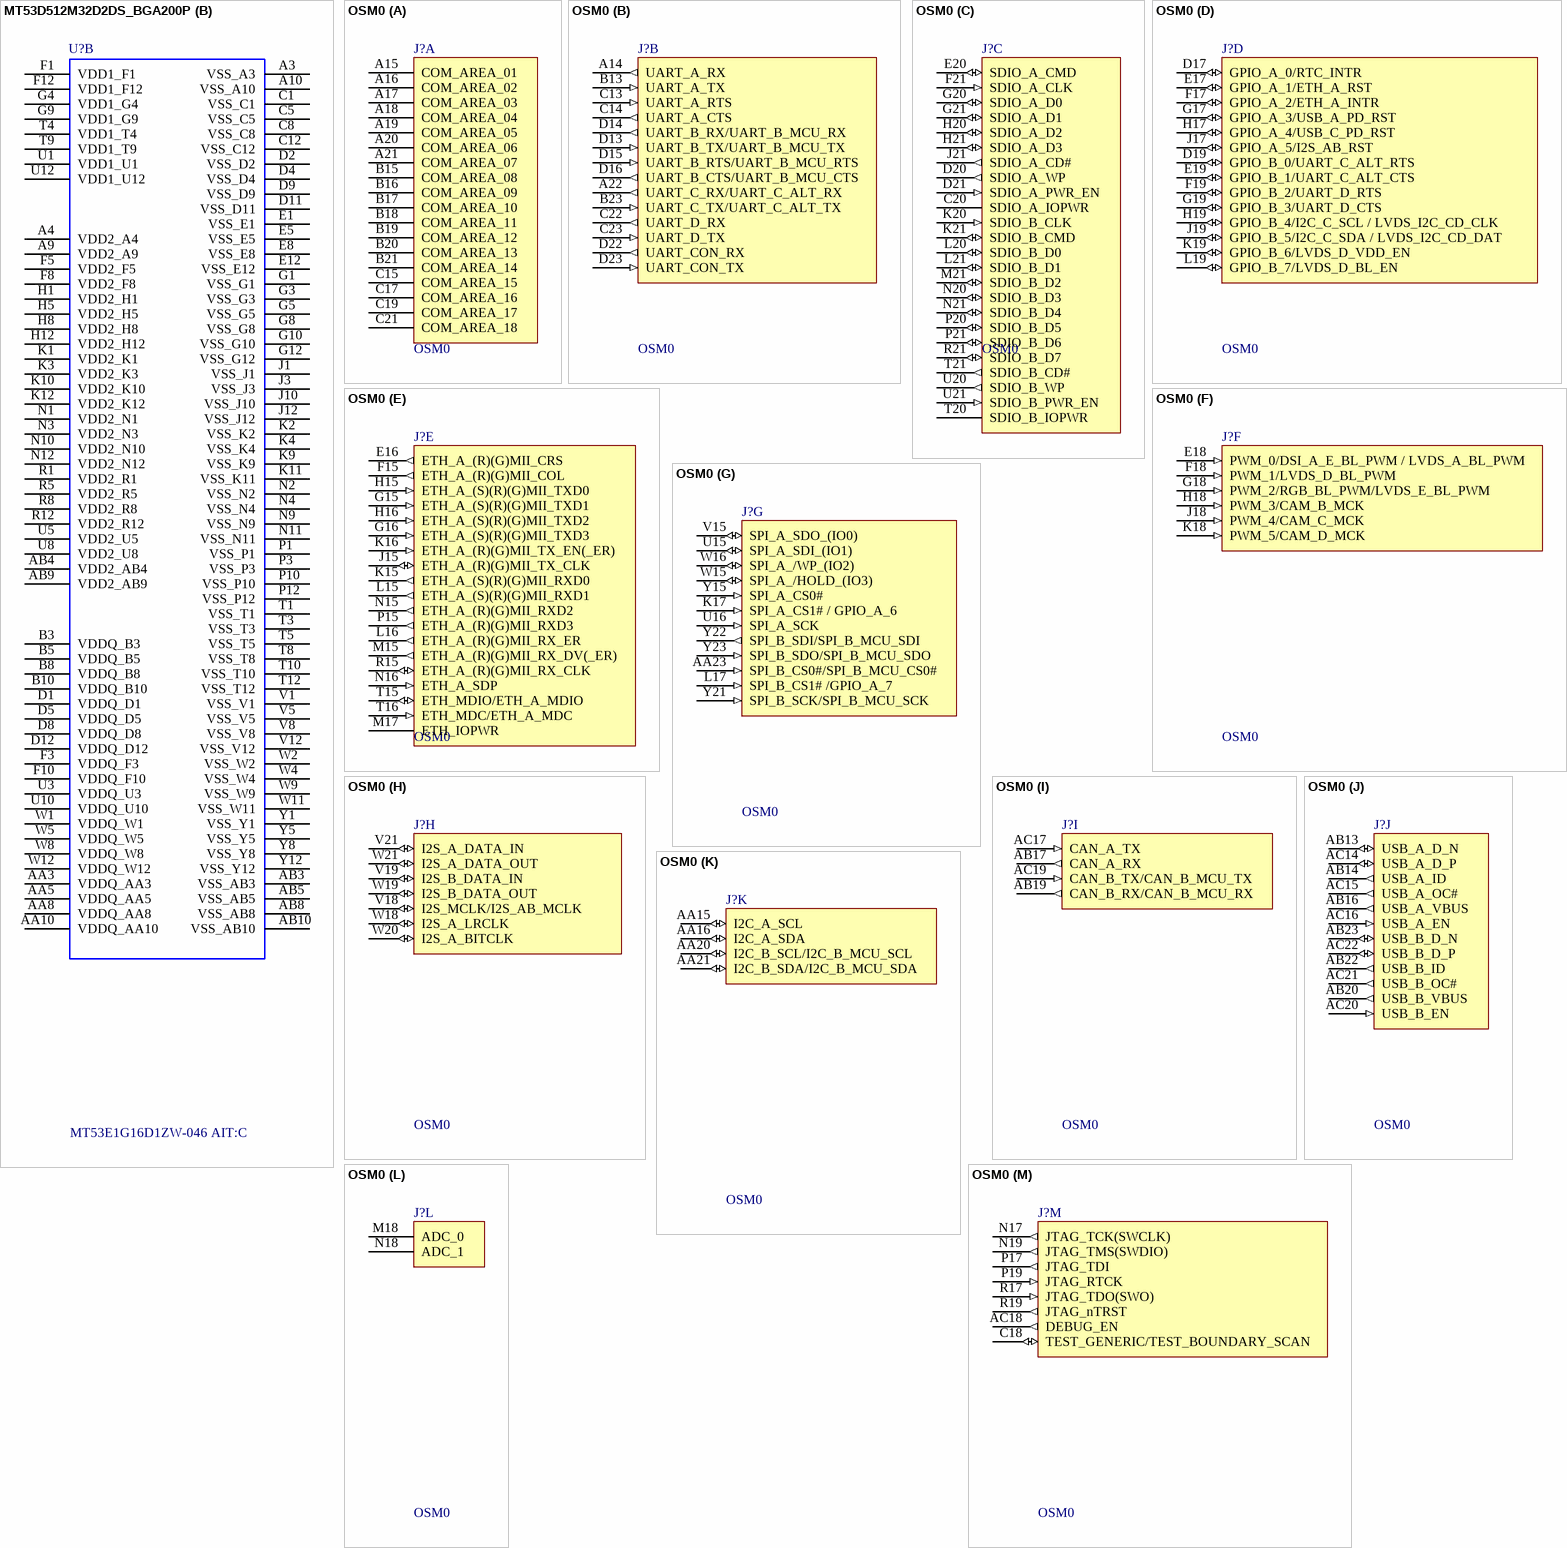
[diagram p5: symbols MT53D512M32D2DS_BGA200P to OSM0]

## MT53D512M32D2DS_BGA200P
designator U?, comment MT53E1G16D1ZW-046 AIT:C
LPDDR4 16G 1GX16 FBGA Industrial Temp; 01. ASET1 UI1: ------------; 01. Set1/BD#: BD3413; 02. Set1/MF1: MICRON; 09. Z Lay/FP: BGA200_0P65X0P8_10P1X14P6
footprint BGA200_0P65X0P8_10P1X14P6
part A pins: A1 DNU_A1, A2 DNU_A2, A5 ZQ0, A8 NC_A8, A11 DNU_A11, A12 DNU_A12, AA1 DNU_AA1, AA2 DQ0_B (io), AA4 DQ7_B (io), AA9 DQ15_B (io), AA11 DQ8_B (io), AA12 DNU_AA12, AB1 DNU_AB1, AB2 DNU_AB2, AB11 DNU_AB11, AB12 DNU_AB12, B1 DNU_B1, B2 DQ0_A (io), B4 DQ7_A (io), B9 DQ15_A (io), B11 DQ8_A (io), B12 DNU_B12, C2 DQ1_A (io), C3 DMI0_A (io), C4 DQ6_A (io), C9 DQ14_A (io), C10 DMI1_A (io), C11 DQ9_A (io), D3 DQS0_t_A (io), D10 DQS1_t_A (io), E2 DQ2_A (io), E3 DQS0_c_A (io), E4 DQ5_A (io), E9 DQ13_A (io), E10 DQS1_c_A (io), E11 DQ10_A (io), F2 DQ3_A (io), F4 DQ4_A (io), F9 DQ12_A (io), F11 DQ11_A (io), G2 ODT_CA_A (in), G11 NC_G11, H2 CA0_A (in), H3 NC_H3, H4 CS0_A (in), H9 CA2_A (in), H10 CA3_A (in), H11 CA4_A (in), J2 CA1_A (in), J4 CKE0_A (in), J5 NC_J5, J8 CK_t_A (in), J9 CK_c_A (in), J11 CA5_A (in), K5 NC_K5, K8 NC_K8, N5 NC_N5, N8 NC_N8, P2 CA1_B (in), P4 CKE0_B (in), P5 NC_P5, P8 CK_t_B (in), P9 CK_c_B (in), P11 CA5_B (in), R2 CA0_B (in), R3 NC_R3, R4 CS0_B (in), R9 CA2_B (in), R10 CA3_B (in), R11 CA4_B (in), T2 ODT_CA_B (in), T11 RESET_N (in), U2 DQ3_B (io), U4 DQ4_B (io), U9 DQ12_B (io), U11 DQ11_B (io), V2 DQ2_B (io), V3 DQS0_c_B (io), V4 DQ5_B (io), V9 DQ13_B (io), V10 DQS1_c_B (io), V11 DQ10_B (io), W3 DQS0_t_B (io), W10 DQS1_t_B (io), Y2 DQ1_B (io), Y3 DMI0_B (io), Y4 DQ6_B (io), Y9 DQ14_B (io), Y10 DMI1_B (io), Y11 DQ9_B (io)
part B pins: A3 VSS_A3 (power), A4 VDD2_A4 (power), A9 VDD2_A9 (power), A10 VSS_A10 (power), AA3 VDDQ_AA3 (power), AA5 VDDQ_AA5 (power), AA8 VDDQ_AA8 (power), AA10 VDDQ_AA10 (power), AB3 VSS_AB3 (power), AB4 VDD2_AB4 (power), AB5 VSS_AB5 (power), AB8 VSS_AB8 (power), AB9 VDD2_AB9 (power), AB10 VSS_AB10 (power), B3 VDDQ_B3 (power), B5 VDDQ_B5 (power), B8 VDDQ_B8 (power), B10 VDDQ_B10 (power), C1 VSS_C1 (power), C5 VSS_C5 (power), C8 VSS_C8 (power), C12 VSS_C12 (power), D1 VDDQ_D1 (power), D2 VSS_D2 (power), D4 VSS_D4 (power), D5 VDDQ_D5 (power), D8 VDDQ_D8 (power), D9 VSS_D9 (power), D11 VSS_D11 (power), D12 VDDQ_D12 (power), E1 VSS_E1 (power), E5 VSS_E5 (power), E8 VSS_E8 (power), E12 VSS_E12 (power), F1 VDD1_F1 (power), F3 VDDQ_F3 (power), F5 VDD2_F5 (power), F8 VDD2_F8 (power), F10 VDDQ_F10 (power), F12 VDD1_F12 (power), G1 VSS_G1 (power), G3 VSS_G3 (power), G4 VDD1_G4 (power), G5 VSS_G5 (power), G8 VSS_G8 (power), G9 VDD1_G9 (power), G10 VSS_G10 (power), G12 VSS_G12 (power), H1 VDD2_H1 (power), H5 VDD2_H5 (power), H8 VDD2_H8 (power), H12 VDD2_H12 (power), J1 VSS_J1 (power), J3 VSS_J3 (power), J10 VSS_J10 (power), J12 VSS_J12 (power), K1 VDD2_K1 (power), K2 VSS_K2 (power), K3 VDD2_K3 (power), K4 VSS_K4 (power), K9 VSS_K9 (power), K10 VDD2_K10 (power), K11 VSS_K11 (power), K12 VDD2_K12 (power), N1 VDD2_N1 (power), N2 VSS_N2 (power), N3 VDD2_N3 (power), N4 VSS_N4 (power), N9 VSS_N9 (power), N10 VDD2_N10 (power), N11 VSS_N11 (power), N12 VDD2_N12 (power), P1 VSS_P1 (power), P3 VSS_P3 (power), P10 VSS_P10 (power), P12 VSS_P12 (power), R1 VDD2_R1 (power), R5 VDD2_R5 (power), R8 VDD2_R8 (power), R12 VDD2_R12 (power), T1 VSS_T1 (power), T3 VSS_T3 (power), T4 VDD1_T4 (power), T5 VSS_T5 (power), T8 VSS_T8 (power), T9 VDD1_T9 (power), T10 VSS_T10 (power), T12 VSS_T12 (power), U1 VDD1_U1 (power), U3 VDDQ_U3 (power), U5 VDD2_U5 (power), U8 VDD2_U8 (power), U10 VDDQ_U10 (power), U12 VDD1_U12 (power), V1 VSS_V1 (power), V5 VSS_V5 (power), V8 VSS_V8 (power), V12 VSS_V12 (power), W1 VDDQ_W1 (power), W2 VSS_W2 (power), W4 VSS_W4 (power), W5 VDDQ_W5 (power), W8 VDDQ_W8 (power), W9 VSS_W9 (power), W11 VSS_W11 (power), W12 VDDQ_W12 (power), Y1 VSS_Y1 (power), Y5 VSS_Y5 (power), Y8 VSS_Y8 (power), Y12 VSS_Y12 (power)

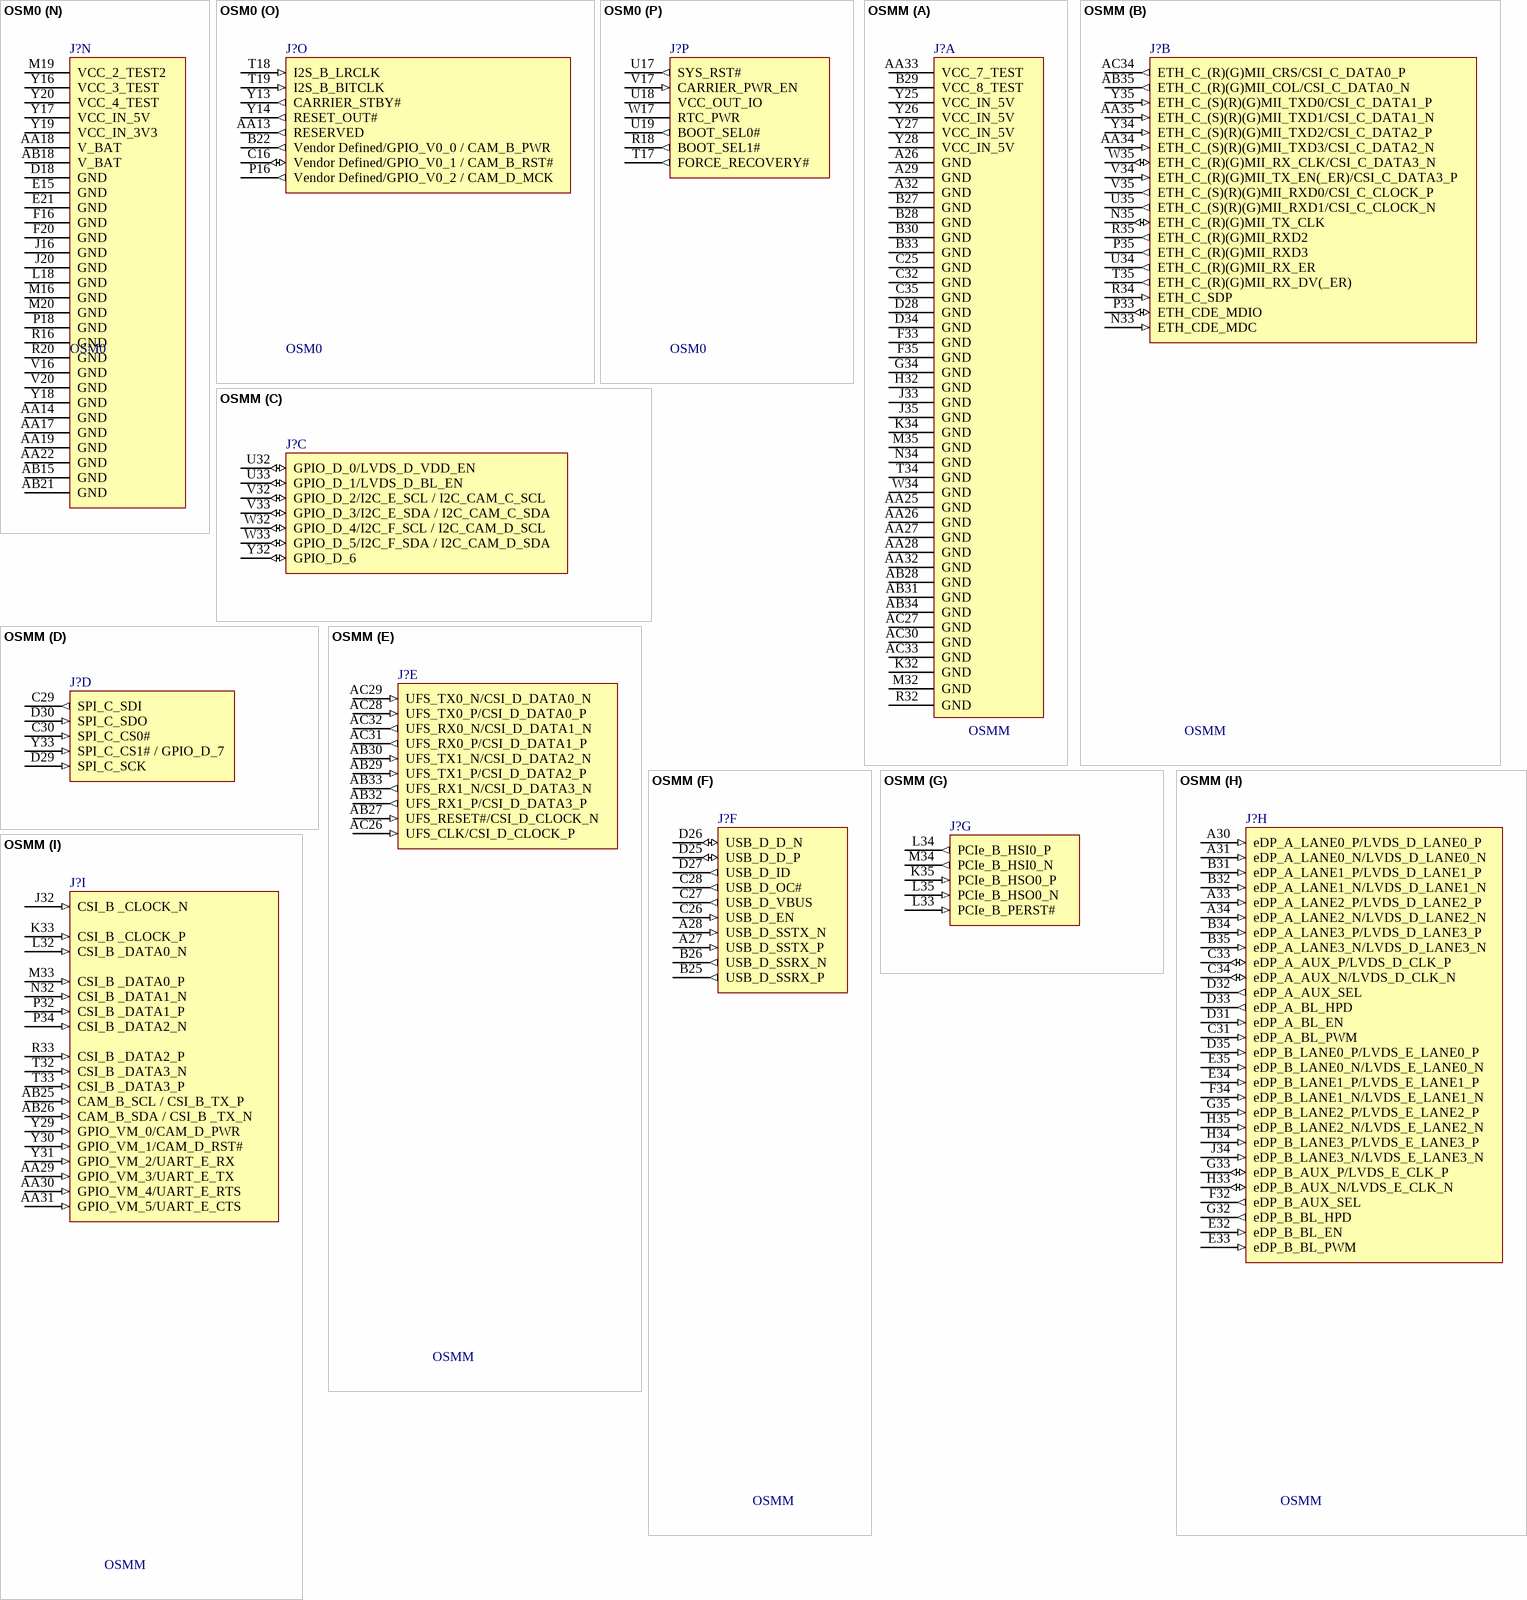
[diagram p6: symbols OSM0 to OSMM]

## OSM0
designator J?  (no BOM)
01. ASET1 UI1: ------------; 09. Z Lay/FP: OSM_M_0
footprint OSM_M_0
part A pins: A15 COM_AREA_01 (power), A16 COM_AREA_02 (power), A17 COM_AREA_03 (power), A18 COM_AREA_04 (power), A19 COM_AREA_05 (power), A20 COM_AREA_06 (power), A21 COM_AREA_07 (power), B15 COM_AREA_08 (power), B16 COM_AREA_09 (power), B17 COM_AREA_10 (power), B18 COM_AREA_11 (power), B19 COM_AREA_12 (power), B20 COM_AREA_13 (power), B21 COM_AREA_14 (power), C15 COM_AREA_15 (power), C17 COM_AREA_16 (power), C19 COM_AREA_17 (power), C21 COM_AREA_18 (power)
part B pins: A14 UART_A_RX (out), A22 UART_C_RX/UART_C_ALT_RX (out), B13 UART_A_TX (in), B23 UART_C_TX/UART_C_ALT_TX (in), C13 UART_A_RTS (in), C14 UART_A_CTS (out), C22 UART_D_RX (out), C23 UART_D_TX (in), D13 UART_B_TX/UART_B_MCU_TX (in), D14 UART_B_RX/UART_B_MCU_RX (out), D15 UART_B_RTS/UART_B_MCU_RTS (in), D16 UART_B_CTS/UART_B_MCU_CTS (out), D22 UART_CON_RX (out), D23 UART_CON_TX (in)
part C pins: C20 SDIO_A_IOPWR (power), D20 SDIO_A_WP (out), D21 SDIO_A_PWR_EN (in), E20 SDIO_A_CMD (io), F21 SDIO_A_CLK (in), G20 SDIO_A_D0 (io), G21 SDIO_A_D1 (io), H20 SDIO_A_D2 (io), H21 SDIO_A_D3 (io), J21 SDIO_A_CD# (out), K20 SDIO_B_CLK (in), K21 SDIO_B_CMD (io), L20 SDIO_B_D0 (io), L21 SDIO_B_D1 (io), M21 SDIO_B_D2 (io), N20 SDIO_B_D3 (io), N21 SDIO_B_D4 (io), P20 SDIO_B_D5 (io), P21 SDIO_B_D6 (io), R21 SDIO_B_D7 (io), T20 SDIO_B_IOPWR (power), T21 SDIO_B_CD# (out), U20 SDIO_B_WP (out), U21 SDIO_B_PWR_EN (in)
part D pins: D17 GPIO_A_0/RTC_INTR (io), D19 GPIO_B_0/UART_C_ALT_RTS (io), E17 GPIO_A_1/ETH_A_RST  (io), E19 GPIO_B_1/UART_C_ALT_CTS (io), F17 GPIO_A_2/ETH_A_INTR (io), F19 GPIO_B_2/UART_D_RTS (io), G17 GPIO_A_3/USB_A_PD_RST  (io), G19 GPIO_B_3/UART_D_CTS  (io), H17 GPIO_A_4/USB_C_PD_RST (io), H19 GPIO_B_4/I2C_C_SCL / LVDS_I2C_CD_CLK (io), J17 GPIO_A_5/I2S_AB_RST (io), J19 GPIO_B_5/I2C_C_SDA / LVDS_I2C_CD_DAT (io), K19 GPIO_B_6/LVDS_D_VDD_EN (io), L19 GPIO_B_7/LVDS_D_BL_EN (io)
part E pins: E16 ETH_A_(R)(G)MII_CRS (out), F15 ETH_A_(R)(G)MII_COL (out), G15 ETH_A_(S)(R)(G)MII_TXD1 (in), G16 ETH_A_(S)(R)(G)MII_TXD3 (in), H15 ETH_A_(S)(R)(G)MII_TXD0 (in), H16 ETH_A_(S)(R)(G)MII_TXD2 (in), J15 ETH_A_(R)(G)MII_TX_CLK (io), K15 ETH_A_(S)(R)(G)MII_RXD0 (out), K16 ETH_A_(R)(G)MII_TX_EN(_ER) (in), L15 ETH_A_(S)(R)(G)MII_RXD1 (out), L16 ETH_A_(R)(G)MII_RX_ER (out), M15 ETH_A_(R)(G)MII_RX_DV(_ER) (out), M17 ETH_IOPWR (power), N15 ETH_A_(R)(G)MII_RXD2 (out), N16 ETH_A_SDP (in), P15 ETH_A_(R)(G)MII_RXD3 (out), R15 ETH_A_(R)(G)MII_RX_CLK (io), T15 ETH_MDIO/ETH_A_MDIO (io), T16 ETH_MDC/ETH_A_MDC (in)
part F pins: E18 PWM_0/DSI_A_E_BL_PWM / LVDS_A_BL_PWM (in), F18 PWM_1/LVDS_D_BL_PWM (in), G18 PWM_2/RGB_BL_PWM/LVDS_E_BL_PWM (in), H18 PWM_3/CAM_B_MCK (in), J18 PWM_4/CAM_C_MCK (in), K18 PWM_5/CAM_D_MCK (in)
part G pins: AA23 SPI_B_CS0#/SPI_B_MCU_CS0# (in), K17 SPI_A_CS1# / GPIO_A_6 (in), L17 SPI_B_CS1# /GPIO_A_7 (in), U15 SPI_A_SDI_(IO1) (io), U16 SPI_A_SCK (in), V15 SPI_A_SDO_(IO0) (io), W15 SPI_A_/HOLD_(IO3) (io), W16 SPI_A_/WP_(IO2) (io), Y15 SPI_A_CS0# (in), Y21 SPI_B_SCK/SPI_B_MCU_SCK (in), Y22 SPI_B_SDI/SPI_B_MCU_SDI (out), Y23 SPI_B_SDO/SPI_B_MCU_SDO (in)
part H pins: V18 I2S_MCLK/I2S_AB_MCLK (io), V19 I2S_B_DATA_IN (io), V21 I2S_A_DATA_IN (io), W18 I2S_A_LRCLK (io), W19 I2S_B_DATA_OUT (io), W20 I2S_A_BITCLK (io), W21 I2S_A_DATA_OUT (io)
part I pins: AB17 CAN_A_RX (out), AB19 CAN_B_RX/CAN_B_MCU_RX (out), AC17 CAN_A_TX (in), AC19 CAN_B_TX/CAN_B_MCU_TX (in)
part J pins: AB13 USB_A_D_N (io), AB14 USB_A_ID (out), AB16 USB_A_VBUS (out), AB20 USB_B_VBUS (out), AB22 USB_B_ID (out), AB23 USB_B_D_N (io), AC14 USB_A_D_P (io), AC15 USB_A_OC# (out), AC16 USB_A_EN (in), AC20 USB_B_EN (in), AC21 USB_B_OC# (out), AC22 USB_B_D_P (io)
part K pins: AA15 I2C_A_SCL (io), AA16 I2C_A_SDA (io), AA20 I2C_B_SCL/I2C_B_MCU_SCL (io), AA21 I2C_B_SDA/I2C_B_MCU_SDA (io)
part L pins: M18 ADC_0 (power), N18 ADC_1 (power)
part M pins: AC18 DEBUG_EN (out), C18 TEST_GENERIC/TEST_BOUNDARY_SCAN  (io), N17 JTAG_TCK(SWCLK) (out), N19 JTAG_TMS(SWDIO) (out), P17 JTAG_TDI (out), P19 JTAG_RTCK (in), R17 JTAG_TDO(SWO) (in), R19 JTAG_nTRST (out)
part N pins: AA14 GND (power), AA17 GND (power), AA18 V_BAT (power), AA19 GND (power), AA22 GND (power), AB15 GND (power), AB18 V_BAT (power), AB21 GND (power), D18 GND (power), E15 GND (power), E21 GND (power), F16 GND (power), F20 GND (power), J16 GND (power), J20 GND (power), L18 GND (power), M16 GND (power), M19 VCC_2_TEST2 (power), M20 GND (power), P18 GND (power), R16 GND (power), R20 GND (power), V16 GND (power), V20 GND (power), Y16 VCC_3_TEST (power), Y17 VCC_IN_5V (power), Y18 GND (power), Y19 VCC_IN_3V3 (power), Y20 VCC_4_TEST (power)
part O pins: AA13 RESERVED (out), B22 Vendor Defined/GPIO_V0_0 / CAM_B_PWR (out), C16 Vendor Defined/GPIO_V0_1 / CAM_B_RST# (io), P16 Vendor Defined/GPIO_V0_2 / CAM_D_MCK (out), T18 I2S_B_LRCLK (in), T19 I2S_B_BITCLK (in), Y13 CARRIER_STBY# (out), Y14 RESET_OUT# (out)
part P pins: R18 BOOT_SEL1# (out), T17 FORCE_RECOVERY# (out), U17 SYS_RST# (out), U18 VCC_OUT_IO (power), U19 BOOT_SEL0# (out), V17 CARRIER_PWR_EN (in), W17 RTC_PWR (power)

## OSMM
designator J?  (no BOM)
01. ASET1 UI1: ------------; 09. Z Lay/FP: OSM_M_M
footprint OSM_M_M
part A pins: A26 GND (power), A29 GND (power), A32 GND (power), AA25 GND (power), AA26 GND (power), AA27 GND (power), AA28 GND (power), AA32 GND (power), AA33 VCC_7_TEST (power), AB28 GND (power), AB31 GND (power), AB34 GND (power), AC27 GND (power), AC30 GND (power), AC33 GND (power), B27 GND (power), B28 GND (power), B29 VCC_8_TEST (power), B30 GND (power), B33 GND (power), C25 GND (power), C32 GND (power), C35 GND (power), D28 GND (power), D34 GND (power), F33 GND (power), F35 GND (power), G34 GND (power), H32 GND (power), J33 GND (power), J35 GND (power), K32 GND, K34 GND (power), M32 GND, M35 GND (power), N34 GND (power), R32 GND, T34 GND (power), W34 GND (power), Y25 VCC_IN_5V (power), Y26 VCC_IN_5V (power), Y27 VCC_IN_5V (power), Y28 VCC_IN_5V (power)
part B pins: AA34 ETH_C_(S)(R)(G)MII_TXD3/CSI_C_DATA2_N (in), AA35 ETH_C_(S)(R)(G)MII_TXD1/CSI_C_DATA1_N (in), AB35 ETH_C_(R)(G)MII_COL/CSI_C_DATA0_N (out), AC34 ETH_C_(R)(G)MII_CRS/CSI_C_DATA0_P (out), N33 ETH_CDE_MDC (in), N35 ETH_C_(R)(G)MII_TX_CLK (io), P33 ETH_CDE_MDIO (io), P35 ETH_C_(R)(G)MII_RXD3 (out), R34 ETH_C_SDP (in), R35 ETH_C_(R)(G)MII_RXD2 (out), T35 ETH_C_(R)(G)MII_RX_DV(_ER) (out), U34 ETH_C_(R)(G)MII_RX_ER (out), U35 ETH_C_(S)(R)(G)MII_RXD1/CSI_C_CLOCK_N (out), V34 ETH_C_(R)(G)MII_TX_EN(_ER)/CSI_C_DATA3_P (in), V35 ETH_C_(S)(R)(G)MII_RXD0/CSI_C_CLOCK_P (out), W35 ETH_C_(R)(G)MII_RX_CLK/CSI_C_DATA3_N (io), Y34 ETH_C_(S)(R)(G)MII_TXD2/CSI_C_DATA2_P (in), Y35 ETH_C_(S)(R)(G)MII_TXD0/CSI_C_DATA1_P (in)
part C pins: U32 GPIO_D_0/LVDS_D_VDD_EN (io), U33 GPIO_D_1/LVDS_D_BL_EN (io), V32 GPIO_D_2/I2C_E_SCL / I2C_CAM_C_SCL (io), V33 GPIO_D_3/I2C_E_SDA / I2C_CAM_C_SDA (io), W32 GPIO_D_4/I2C_F_SCL / I2C_CAM_D_SCL (io), W33 GPIO_D_5/I2C_F_SDA / I2C_CAM_D_SDA (io), Y32 GPIO_D_6 (io)
part D pins: C29 SPI_C_SDI (out), C30 SPI_C_CS0# (in), D29 SPI_C_SCK (in), D30 SPI_C_SDO (in), Y33 SPI_C_CS1# / GPIO_D_7 (in)
part E pins: AB27 UFS_RESET#/CSI_D_CLOCK_N (in), AB29 UFS_TX1_P/CSI_D_DATA2_P (in), AB30 UFS_TX1_N/CSI_D_DATA2_N (in), AB32 UFS_RX1_P/CSI_D_DATA3_P (out), AB33 UFS_RX1_N/CSI_D_DATA3_N (out), AC26 UFS_CLK/CSI_D_CLOCK_P (in), AC28 UFS_TX0_P/CSI_D_DATA0_P (in), AC29 UFS_TX0_N/CSI_D_DATA0_N (in), AC31 UFS_RX0_P/CSI_D_DATA1_P (out), AC32 UFS_RX0_N/CSI_D_DATA1_N (out)
part F pins: A27 USB_D_SSTX_P (in), A28 USB_D_SSTX_N (in), B25 USB_D_SSRX_P (out), B26 USB_D_SSRX_N (out), C26 USB_D_EN (in), C27 USB_D_VBUS (out), C28 USB_D_OC# (out), D25 USB_D_D_P (io), D26 USB_D_D_N (io), D27 USB_D_ID (out)
part G pins: K35 PCIe_B_HSO0_P (in), L33 PCIe_B_PERST# (in), L34 PCIe_B_HSI0_P (out), L35 PCIe_B_HSO0_N (in), M34 PCIe_B_HSI0_N (out)
part H pins: A30 eDP_A_LANE0_P/LVDS_D_LANE0_P (in), A31 eDP_A_LANE0_N/LVDS_D_LANE0_N (in), A33 eDP_A_LANE2_P/LVDS_D_LANE2_P (in), A34 eDP_A_LANE2_N/LVDS_D_LANE2_N (in), B31 eDP_A_LANE1_P/LVDS_D_LANE1_P (in), B32 eDP_A_LANE1_N/LVDS_D_LANE1_N (in), B34 eDP_A_LANE3_P/LVDS_D_LANE3_P (in), B35 eDP_A_LANE3_N/LVDS_D_LANE3_N (in), C31 eDP_A_BL_PWM (in), C33 eDP_A_AUX_P/LVDS_D_CLK_P (io), C34 eDP_A_AUX_N/LVDS_D_CLK_N (io), D31 eDP_A_BL_EN (in), D32 eDP_A_AUX_SEL (out), D33 eDP_A_BL_HPD (out), D35 eDP_B_LANE0_P/LVDS_E_LANE0_P (in), E32 eDP_B_BL_EN (in), E33 eDP_B_BL_PWM (in), E34 eDP_B_LANE1_P/LVDS_E_LANE1_P (in), E35 eDP_B_LANE0_N/LVDS_E_LANE0_N (in), F32 eDP_B_AUX_SEL (out), F34 eDP_B_LANE1_N/LVDS_E_LANE1_N (in), G32 eDP_B_BL_HPD (out), G33 eDP_B_AUX_P/LVDS_E_CLK_P (io), G35 eDP_B_LANE2_P/LVDS_E_LANE2_P (in), H33 eDP_B_AUX_N/LVDS_E_CLK_N (io), H34 eDP_B_LANE3_P/LVDS_E_LANE3_P (in), H35 eDP_B_LANE2_N/LVDS_E_LANE2_N (in), J34 eDP_B_LANE3_N/LVDS_E_LANE3_N (in)
part I pins: AA29 GPIO_VM_3/UART_E_TX (in), AA30 GPIO_VM_4/UART_E_RTS (in), AA31 GPIO_VM_5/UART_E_CTS (in), AB25 CAM_B_SCL / CSI_B_TX_P (in), AB26 CAM_B_SDA / CSI_B _TX_N (in), J32 CSI_B _CLOCK_N (in), K33 CSI_B _CLOCK_P (in), L32 CSI_B _DATA0_N (in), M33 CSI_B _DATA0_P (in), N32 CSI_B _DATA1_N (in), P32 CSI_B _DATA1_P (in), P34 CSI_B _DATA2_N (in), R33 CSI_B _DATA2_P (in), T32 CSI_B _DATA3_N (in), T33 CSI_B _DATA3_P (in), Y29 GPIO_VM_0/CAM_D_PWR (in), Y30 GPIO_VM_1/CAM_D_RST# (in), Y31 GPIO_VM_2/UART_E_RX (in)

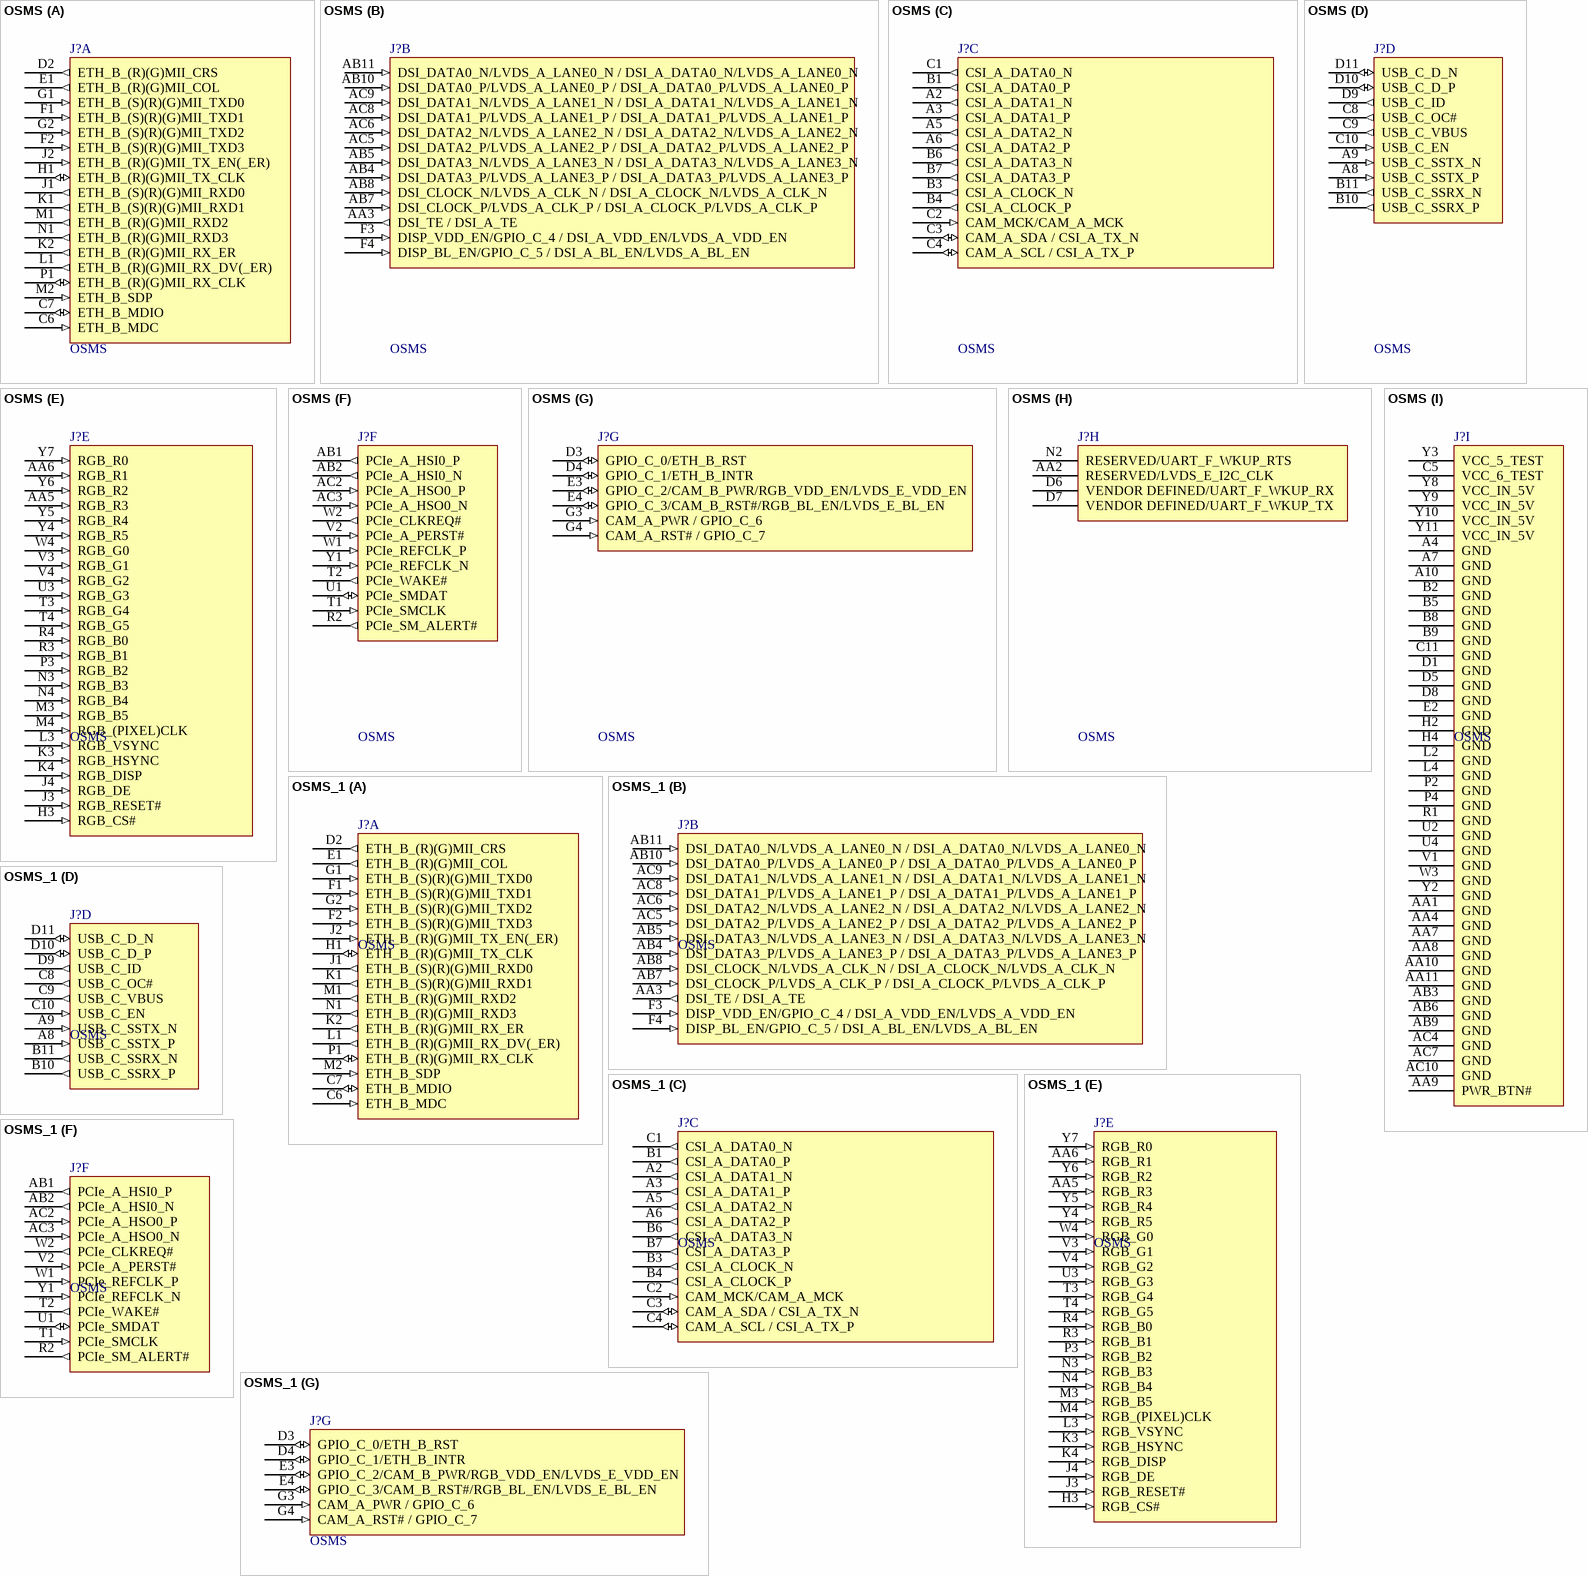
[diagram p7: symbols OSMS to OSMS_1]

## OSMS
designator J?  (no BOM)
01. ASET1 UI1: ------------; 09. Z Lay/FP: OSM_M_S
footprint OSM_M_S
part A pins: C6 ETH_B_MDC (in), C7 ETH_B_MDIO (io), D2 ETH_B_(R)(G)MII_CRS (out), E1 ETH_B_(R)(G)MII_COL (out), F1 ETH_B_(S)(R)(G)MII_TXD1 (in), F2 ETH_B_(S)(R)(G)MII_TXD3 (in), G1 ETH_B_(S)(R)(G)MII_TXD0 (in), G2 ETH_B_(S)(R)(G)MII_TXD2 (in), H1 ETH_B_(R)(G)MII_TX_CLK (io), J1 ETH_B_(S)(R)(G)MII_RXD0 (out), J2 ETH_B_(R)(G)MII_TX_EN(_ER) (in), K1 ETH_B_(S)(R)(G)MII_RXD1 (out), K2 ETH_B_(R)(G)MII_RX_ER (out), L1 ETH_B_(R)(G)MII_RX_DV(_ER) (out), M1 ETH_B_(R)(G)MII_RXD2 (out), M2 ETH_B_SDP (in), N1 ETH_B_(R)(G)MII_RXD3 (out), P1 ETH_B_(R)(G)MII_RX_CLK (io)
part B pins: AA3 DSI_TE / DSI_A_TE (out), AB4 DSI_DATA3_P/LVDS_A_LANE3_P / DSI_A_DATA3_P/LVDS_A_LANE3_P (in), AB5 DSI_DATA3_N/LVDS_A_LANE3_N / DSI_A_DATA3_N/LVDS_A_LANE3_N (in), AB7 DSI_CLOCK_P/LVDS_A_CLK_P / DSI_A_CLOCK_P/LVDS_A_CLK_P (in), AB8 DSI_CLOCK_N/LVDS_A_CLK_N / DSI_A_CLOCK_N/LVDS_A_CLK_N (in), AB10 DSI_DATA0_P/LVDS_A_LANE0_P / DSI_A_DATA0_P/LVDS_A_LANE0_P (in), AB11 DSI_DATA0_N/LVDS_A_LANE0_N / DSI_A_DATA0_N/LVDS_A_LANE0_N (in), AC5 DSI_DATA2_P/LVDS_A_LANE2_P / DSI_A_DATA2_P/LVDS_A_LANE2_P (in), AC6 DSI_DATA2_N/LVDS_A_LANE2_N / DSI_A_DATA2_N/LVDS_A_LANE2_N (in), AC8 DSI_DATA1_P/LVDS_A_LANE1_P / DSI_A_DATA1_P/LVDS_A_LANE1_P (in), AC9 DSI_DATA1_N/LVDS_A_LANE1_N / DSI_A_DATA1_N/LVDS_A_LANE1_N (in), F3 DISP_VDD_EN/GPIO_C_4 / DSI_A_VDD_EN/LVDS_A_VDD_EN (in), F4 DISP_BL_EN/GPIO_C_5 / DSI_A_BL_EN/LVDS_A_BL_EN (in)
part C pins: A2 CSI_A_DATA1_N (out), A3 CSI_A_DATA1_P (out), A5 CSI_A_DATA2_N (out), A6 CSI_A_DATA2_P (out), B1 CSI_A_DATA0_P (out), B3 CSI_A_CLOCK_N (out), B4 CSI_A_CLOCK_P (out), B6 CSI_A_DATA3_N (out), B7 CSI_A_DATA3_P (out), C1 CSI_A_DATA0_N (out), C2 CAM_MCK/CAM_A_MCK (in), C3 CAM_A_SDA / CSI_A_TX_N (io), C4 CAM_A_SCL / CSI_A_TX_P (io)
part D pins: A8 USB_C_SSTX_P (in), A9 USB_C_SSTX_N (in), B10 USB_C_SSRX_P (out), B11 USB_C_SSRX_N (out), C8 USB_C_OC# (out), C9 USB_C_VBUS (out), C10 USB_C_EN (in), D9 USB_C_ID (out), D10 USB_C_D_P (io), D11 USB_C_D_N (io)
part E pins: AA5 RGB_R3 (in), AA6 RGB_R1 (in), H3 RGB_CS# (in), J3 RGB_RESET# (in), J4 RGB_DE (in), K3 RGB_HSYNC (in), K4 RGB_DISP (in), L3 RGB_VSYNC (in), M3 RGB_B5 (in), M4 RGB_(PIXEL)CLK (in), N3 RGB_B3 (in), N4 RGB_B4 (in), P3 RGB_B2 (in), R3 RGB_B1 (in), R4 RGB_B0 (in), T3 RGB_G4 (in), T4 RGB_G5 (in), U3 RGB_G3 (in), V3 RGB_G1 (in), V4 RGB_G2 (in), W4 RGB_G0 (in), Y4 RGB_R5 (in), Y5 RGB_R4 (in), Y6 RGB_R2 (in), Y7 RGB_R0 (in)
part F pins: AB1 PCIe_A_HSI0_P (out), AB2 PCIe_A_HSI0_N (out), AC2 PCIe_A_HSO0_P (in), AC3 PCIe_A_HSO0_N (in), R2 PCIe_SM_ALERT# (out), T1 PCIe_SMCLK (in), T2 PCIe_WAKE# (out), U1 PCIe_SMDAT (io), V2 PCIe_A_PERST# (in), W1 PCIe_REFCLK_P (in), W2 PCIe_CLKREQ# (out), Y1 PCIe_REFCLK_N (in)
part G pins: D3 GPIO_C_0/ETH_B_RST (io), D4 GPIO_C_1/ETH_B_INTR (io), E3 GPIO_C_2/CAM_B_PWR/RGB_VDD_EN/LVDS_E_VDD_EN (io), E4 GPIO_C_3/CAM_B_RST#/RGB_BL_EN/LVDS_E_BL_EN (io), G3 CAM_A_PWR / GPIO_C_6 (in), G4 CAM_A_RST# / GPIO_C_7 (in)
part H pins: AA2 RESERVED/LVDS_E_I2C_CLK, D6 VENDOR DEFINED/UART_F_WKUP_RX, D7 VENDOR DEFINED/UART_F_WKUP_TX, N2 RESERVED/UART_F_WKUP_RTS
part I pins: A4 GND (power), A7 GND (power), A10 GND (power), AA1 GND (power), AA4 GND (power), AA7 GND (power), AA8 GND (power), AA9 PWR_BTN# (power), AA10 GND (power), AA11 GND (power), AB3 GND (power), AB6 GND (power), AB9 GND (power), AC4 GND (power), AC7 GND (power), AC10 GND (power), B2 GND (power), B5 GND (power), B8 GND (power), B9 GND (power), C5 VCC_6_TEST (power), C11 GND (power), D1 GND (power), D5 GND (power), D8 GND (power), E2 GND (power), H2 GND (power), H4 GND (power), L2 GND (power), L4 GND (power), P2 GND (power), P4 GND (power), R1 GND (power), U2 GND (power), U4 GND (power), V1 GND (power), W3 GND (power), Y2 GND (power), Y3 VCC_5_TEST (power), Y8 VCC_IN_5V (power), Y9 VCC_IN_5V (power), Y10 VCC_IN_5V (power), Y11 VCC_IN_5V (power)

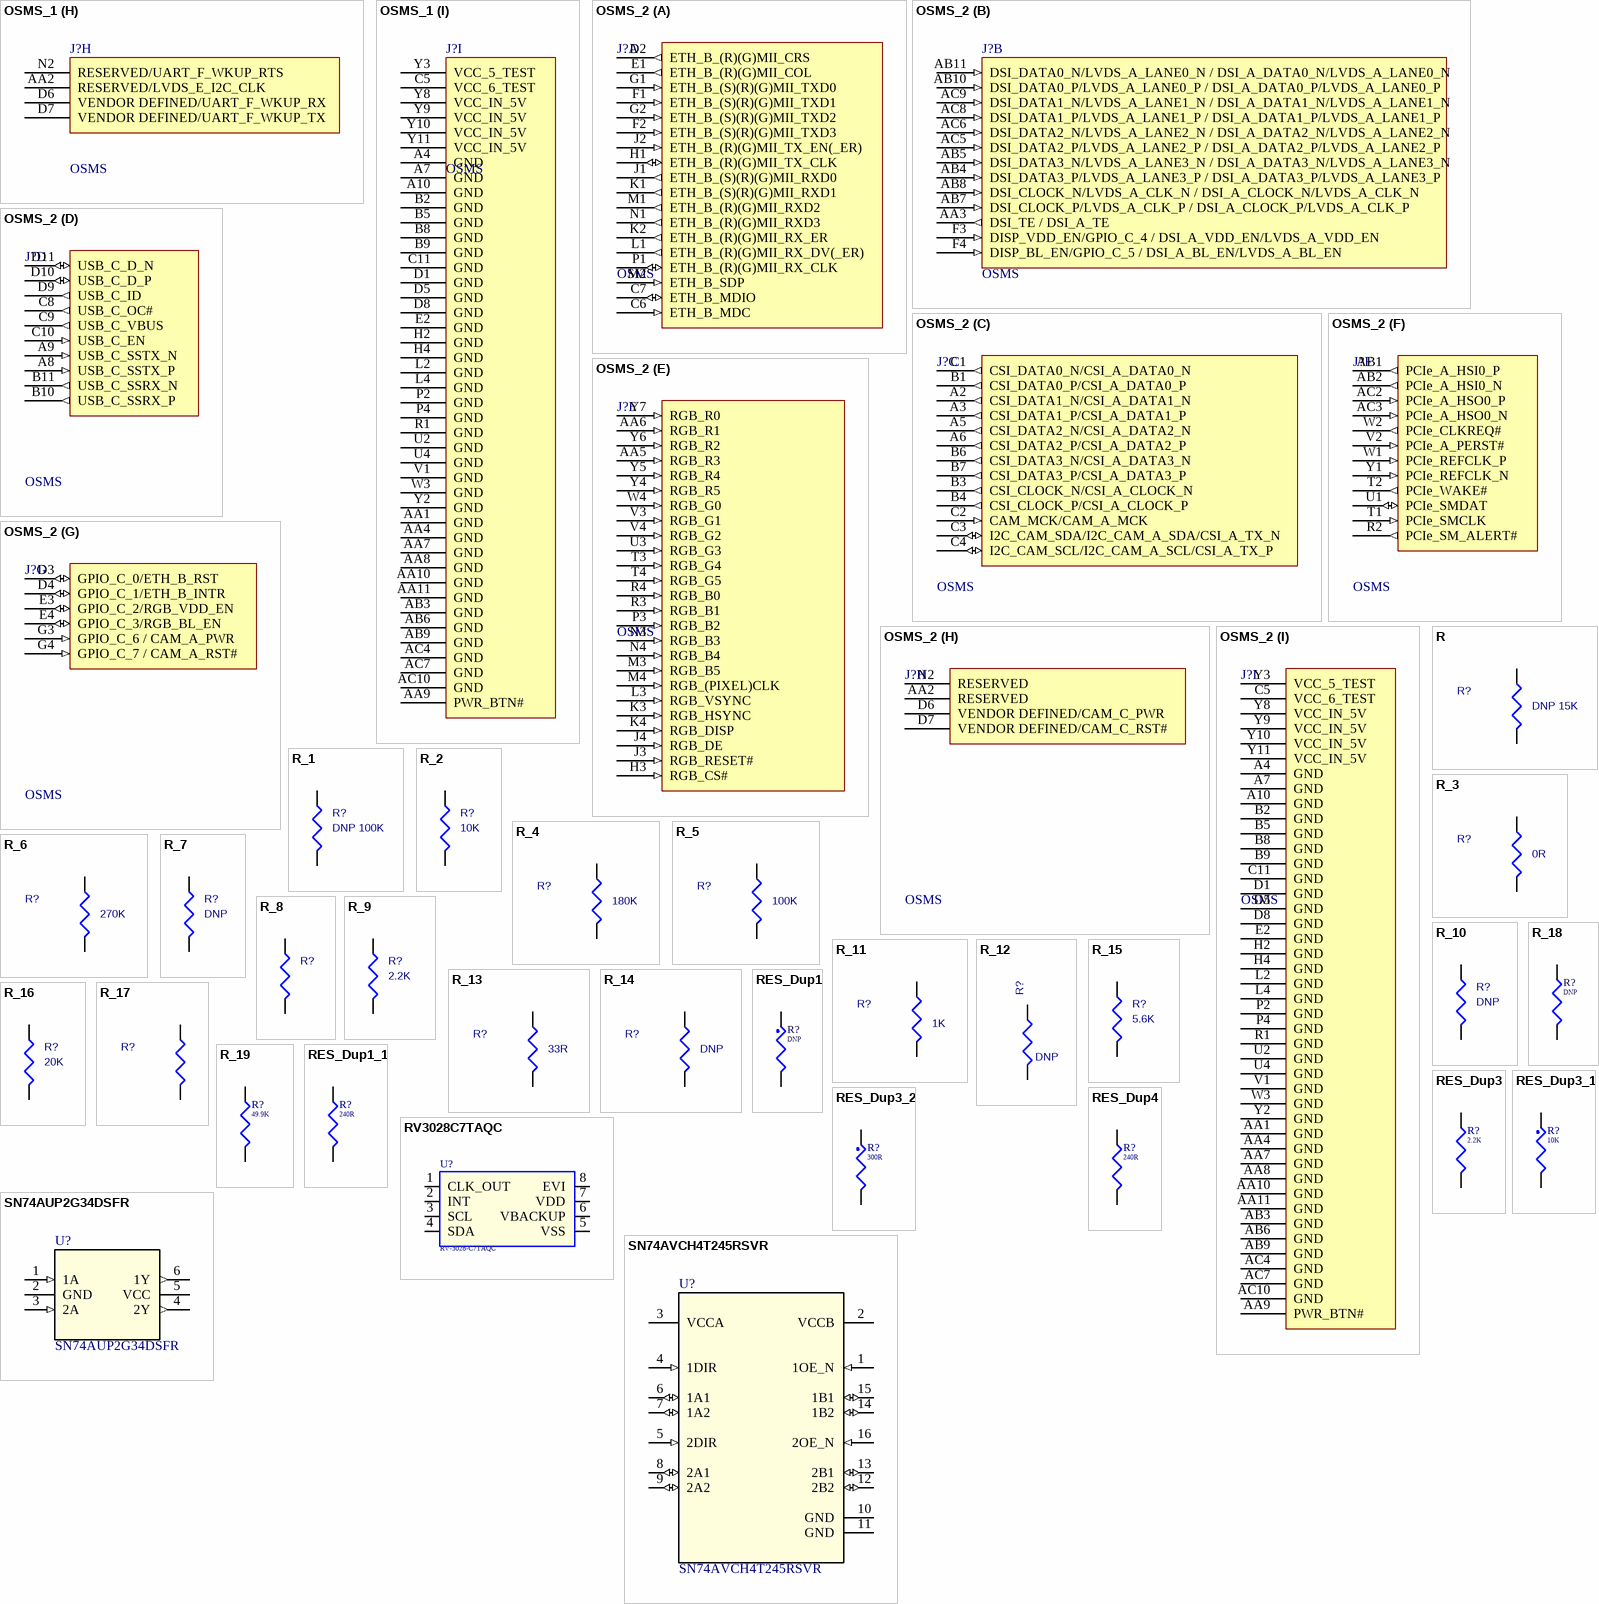
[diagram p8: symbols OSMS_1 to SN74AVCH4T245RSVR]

## OSMS_1
designator J?, comment OSMS  (no BOM)
01. ASET1 UI1: ------------; 09. Z Lay/FP: OSM_M_S
footprint OSM_M_S
part A pins: C6 ETH_B_MDC (in), C7 ETH_B_MDIO (io), D2 ETH_B_(R)(G)MII_CRS (out), E1 ETH_B_(R)(G)MII_COL (out), F1 ETH_B_(S)(R)(G)MII_TXD1 (in), F2 ETH_B_(S)(R)(G)MII_TXD3 (in), G1 ETH_B_(S)(R)(G)MII_TXD0 (in), G2 ETH_B_(S)(R)(G)MII_TXD2 (in), H1 ETH_B_(R)(G)MII_TX_CLK (io), J1 ETH_B_(S)(R)(G)MII_RXD0 (out), J2 ETH_B_(R)(G)MII_TX_EN(_ER) (in), K1 ETH_B_(S)(R)(G)MII_RXD1 (out), K2 ETH_B_(R)(G)MII_RX_ER (out), L1 ETH_B_(R)(G)MII_RX_DV(_ER) (out), M1 ETH_B_(R)(G)MII_RXD2 (out), M2 ETH_B_SDP (in), N1 ETH_B_(R)(G)MII_RXD3 (out), P1 ETH_B_(R)(G)MII_RX_CLK (io)
part B pins: AA3 DSI_TE / DSI_A_TE (out), AB4 DSI_DATA3_P/LVDS_A_LANE3_P / DSI_A_DATA3_P/LVDS_A_LANE3_P (in), AB5 DSI_DATA3_N/LVDS_A_LANE3_N / DSI_A_DATA3_N/LVDS_A_LANE3_N (in), AB7 DSI_CLOCK_P/LVDS_A_CLK_P / DSI_A_CLOCK_P/LVDS_A_CLK_P (in), AB8 DSI_CLOCK_N/LVDS_A_CLK_N / DSI_A_CLOCK_N/LVDS_A_CLK_N (in), AB10 DSI_DATA0_P/LVDS_A_LANE0_P / DSI_A_DATA0_P/LVDS_A_LANE0_P (in), AB11 DSI_DATA0_N/LVDS_A_LANE0_N / DSI_A_DATA0_N/LVDS_A_LANE0_N (in), AC5 DSI_DATA2_P/LVDS_A_LANE2_P / DSI_A_DATA2_P/LVDS_A_LANE2_P (in), AC6 DSI_DATA2_N/LVDS_A_LANE2_N / DSI_A_DATA2_N/LVDS_A_LANE2_N (in), AC8 DSI_DATA1_P/LVDS_A_LANE1_P / DSI_A_DATA1_P/LVDS_A_LANE1_P (in), AC9 DSI_DATA1_N/LVDS_A_LANE1_N / DSI_A_DATA1_N/LVDS_A_LANE1_N (in), F3 DISP_VDD_EN/GPIO_C_4 / DSI_A_VDD_EN/LVDS_A_VDD_EN (in), F4 DISP_BL_EN/GPIO_C_5 / DSI_A_BL_EN/LVDS_A_BL_EN (in)
part C pins: A2 CSI_A_DATA1_N (out), A3 CSI_A_DATA1_P (out), A5 CSI_A_DATA2_N (out), A6 CSI_A_DATA2_P (out), B1 CSI_A_DATA0_P (out), B3 CSI_A_CLOCK_N (out), B4 CSI_A_CLOCK_P (out), B6 CSI_A_DATA3_N (out), B7 CSI_A_DATA3_P (out), C1 CSI_A_DATA0_N (out), C2 CAM_MCK/CAM_A_MCK (in), C3 CAM_A_SDA / CSI_A_TX_N (io), C4 CAM_A_SCL / CSI_A_TX_P (io)
part D pins: A8 USB_C_SSTX_P (in), A9 USB_C_SSTX_N (in), B10 USB_C_SSRX_P (out), B11 USB_C_SSRX_N (out), C8 USB_C_OC# (out), C9 USB_C_VBUS (out), C10 USB_C_EN (in), D9 USB_C_ID (out), D10 USB_C_D_P (io), D11 USB_C_D_N (io)
part E pins: AA5 RGB_R3 (in), AA6 RGB_R1 (in), H3 RGB_CS# (in), J3 RGB_RESET# (in), J4 RGB_DE (in), K3 RGB_HSYNC (in), K4 RGB_DISP (in), L3 RGB_VSYNC (in), M3 RGB_B5 (in), M4 RGB_(PIXEL)CLK (in), N3 RGB_B3 (in), N4 RGB_B4 (in), P3 RGB_B2 (in), R3 RGB_B1 (in), R4 RGB_B0 (in), T3 RGB_G4 (in), T4 RGB_G5 (in), U3 RGB_G3 (in), V3 RGB_G1 (in), V4 RGB_G2 (in), W4 RGB_G0 (in), Y4 RGB_R5 (in), Y5 RGB_R4 (in), Y6 RGB_R2 (in), Y7 RGB_R0 (in)
part F pins: AB1 PCIe_A_HSI0_P (out), AB2 PCIe_A_HSI0_N (out), AC2 PCIe_A_HSO0_P (in), AC3 PCIe_A_HSO0_N (in), R2 PCIe_SM_ALERT# (out), T1 PCIe_SMCLK (in), T2 PCIe_WAKE# (out), U1 PCIe_SMDAT (io), V2 PCIe_A_PERST# (in), W1 PCIe_REFCLK_P (in), W2 PCIe_CLKREQ# (out), Y1 PCIe_REFCLK_N (in)
part G pins: D3 GPIO_C_0/ETH_B_RST (io), D4 GPIO_C_1/ETH_B_INTR (io), E3 GPIO_C_2/CAM_B_PWR/RGB_VDD_EN/LVDS_E_VDD_EN (io), E4 GPIO_C_3/CAM_B_RST#/RGB_BL_EN/LVDS_E_BL_EN (io), G3 CAM_A_PWR / GPIO_C_6 (in), G4 CAM_A_RST# / GPIO_C_7 (in)
part H pins: AA2 RESERVED/LVDS_E_I2C_CLK, D6 VENDOR DEFINED/UART_F_WKUP_RX, D7 VENDOR DEFINED/UART_F_WKUP_TX, N2 RESERVED/UART_F_WKUP_RTS
part I pins: A4 GND (power), A7 GND (power), A10 GND (power), AA1 GND (power), AA4 GND (power), AA7 GND (power), AA8 GND (power), AA9 PWR_BTN# (power), AA10 GND (power), AA11 GND (power), AB3 GND (power), AB6 GND (power), AB9 GND (power), AC4 GND (power), AC7 GND (power), AC10 GND (power), B2 GND (power), B5 GND (power), B8 GND (power), B9 GND (power), C5 VCC_6_TEST (power), C11 GND (power), D1 GND (power), D5 GND (power), D8 GND (power), E2 GND (power), H2 GND (power), H4 GND (power), L2 GND (power), L4 GND (power), P2 GND (power), P4 GND (power), R1 GND (power), U2 GND (power), U4 GND (power), V1 GND (power), W3 GND (power), Y2 GND (power), Y3 VCC_5_TEST (power), Y8 VCC_IN_5V (power), Y9 VCC_IN_5V (power), Y10 VCC_IN_5V (power), Y11 VCC_IN_5V (power)

## OSMS_2
designator J?, comment OSMS  (no BOM)
01. ASET1 UI1: ------------; 09. Z Lay/FP: OSM_M_S
footprint OSM_M_S
part A pins: C6 ETH_B_MDC (in), C7 ETH_B_MDIO (io), D2 ETH_B_(R)(G)MII_CRS (out), E1 ETH_B_(R)(G)MII_COL (out), F1 ETH_B_(S)(R)(G)MII_TXD1 (in), F2 ETH_B_(S)(R)(G)MII_TXD3 (in), G1 ETH_B_(S)(R)(G)MII_TXD0 (in), G2 ETH_B_(S)(R)(G)MII_TXD2 (in), H1 ETH_B_(R)(G)MII_TX_CLK (io), J1 ETH_B_(S)(R)(G)MII_RXD0 (out), J2 ETH_B_(R)(G)MII_TX_EN(_ER) (in), K1 ETH_B_(S)(R)(G)MII_RXD1 (out), K2 ETH_B_(R)(G)MII_RX_ER (out), L1 ETH_B_(R)(G)MII_RX_DV(_ER) (out), M1 ETH_B_(R)(G)MII_RXD2 (out), M2 ETH_B_SDP (in), N1 ETH_B_(R)(G)MII_RXD3 (out), P1 ETH_B_(R)(G)MII_RX_CLK (io)
part B pins: AA3 DSI_TE / DSI_A_TE (out), AB4 DSI_DATA3_P/LVDS_A_LANE3_P / DSI_A_DATA3_P/LVDS_A_LANE3_P (in), AB5 DSI_DATA3_N/LVDS_A_LANE3_N / DSI_A_DATA3_N/LVDS_A_LANE3_N (in), AB7 DSI_CLOCK_P/LVDS_A_CLK_P / DSI_A_CLOCK_P/LVDS_A_CLK_P (in), AB8 DSI_CLOCK_N/LVDS_A_CLK_N / DSI_A_CLOCK_N/LVDS_A_CLK_N (in), AB10 DSI_DATA0_P/LVDS_A_LANE0_P / DSI_A_DATA0_P/LVDS_A_LANE0_P (in), AB11 DSI_DATA0_N/LVDS_A_LANE0_N / DSI_A_DATA0_N/LVDS_A_LANE0_N (in), AC5 DSI_DATA2_P/LVDS_A_LANE2_P / DSI_A_DATA2_P/LVDS_A_LANE2_P (in), AC6 DSI_DATA2_N/LVDS_A_LANE2_N / DSI_A_DATA2_N/LVDS_A_LANE2_N (in), AC8 DSI_DATA1_P/LVDS_A_LANE1_P / DSI_A_DATA1_P/LVDS_A_LANE1_P (in), AC9 DSI_DATA1_N/LVDS_A_LANE1_N / DSI_A_DATA1_N/LVDS_A_LANE1_N (in), F3 DISP_VDD_EN/GPIO_C_4 / DSI_A_VDD_EN/LVDS_A_VDD_EN (in), F4 DISP_BL_EN/GPIO_C_5 / DSI_A_BL_EN/LVDS_A_BL_EN (in)
part C pins: A2 CSI_DATA1_N/CSI_A_DATA1_N (out), A3 CSI_DATA1_P/CSI_A_DATA1_P (out), A5 CSI_DATA2_N/CSI_A_DATA2_N (out), A6 CSI_DATA2_P/CSI_A_DATA2_P (out), B1 CSI_DATA0_P/CSI_A_DATA0_P (out), B3 CSI_CLOCK_N/CSI_A_CLOCK_N (out), B4 CSI_CLOCK_P/CSI_A_CLOCK_P (out), B6 CSI_DATA3_N/CSI_A_DATA3_N (out), B7 CSI_DATA3_P/CSI_A_DATA3_P (out), C1 CSI_DATA0_N/CSI_A_DATA0_N (out), C2 CAM_MCK/CAM_A_MCK (in), C3 I2C_CAM_SDA/I2C_CAM_A_SDA/CSI_A_TX_N (io), C4 I2C_CAM_SCL/I2C_CAM_A_SCL/CSI_A_TX_P (io)
part D pins: A8 USB_C_SSTX_P (in), A9 USB_C_SSTX_N (in), B10 USB_C_SSRX_P (out), B11 USB_C_SSRX_N (out), C8 USB_C_OC# (out), C9 USB_C_VBUS (out), C10 USB_C_EN (in), D9 USB_C_ID (out), D10 USB_C_D_P (io), D11 USB_C_D_N (io)
part E pins: AA5 RGB_R3 (in), AA6 RGB_R1 (in), H3 RGB_CS# (in), J3 RGB_RESET# (in), J4 RGB_DE (in), K3 RGB_HSYNC (in), K4 RGB_DISP (in), L3 RGB_VSYNC (in), M3 RGB_B5 (in), M4 RGB_(PIXEL)CLK (in), N3 RGB_B3 (in), N4 RGB_B4 (in), P3 RGB_B2 (in), R3 RGB_B1 (in), R4 RGB_B0 (in), T3 RGB_G4 (in), T4 RGB_G5 (in), U3 RGB_G3 (in), V3 RGB_G1 (in), V4 RGB_G2 (in), W4 RGB_G0 (in), Y4 RGB_R5 (in), Y5 RGB_R4 (in), Y6 RGB_R2 (in), Y7 RGB_R0 (in)
part F pins: AB1 PCIe_A_HSI0_P (out), AB2 PCIe_A_HSI0_N (out), AC2 PCIe_A_HSO0_P (in), AC3 PCIe_A_HSO0_N (in), R2 PCIe_SM_ALERT# (out), T1 PCIe_SMCLK (in), T2 PCIe_WAKE# (out), U1 PCIe_SMDAT (io), V2 PCIe_A_PERST# (in), W1 PCIe_REFCLK_P (in), W2 PCIe_CLKREQ# (out), Y1 PCIe_REFCLK_N (in)
part G pins: D3 GPIO_C_0/ETH_B_RST (io), D4 GPIO_C_1/ETH_B_INTR (io), E3 GPIO_C_2/RGB_VDD_EN (io), E4 GPIO_C_3/RGB_BL_EN (io), G3 GPIO_C_6 / CAM_A_PWR (in), G4 GPIO_C_7 / CAM_A_RST# (in)
part H pins: AA2 RESERVED, D6 VENDOR DEFINED/CAM_C_PWR, D7 VENDOR DEFINED/CAM_C_RST#, N2 RESERVED
part I pins: A4 GND (power), A7 GND (power), A10 GND (power), AA1 GND (power), AA4 GND (power), AA7 GND (power), AA8 GND (power), AA9 PWR_BTN# (power), AA10 GND (power), AA11 GND (power), AB3 GND (power), AB6 GND (power), AB9 GND (power), AC4 GND (power), AC7 GND (power), AC10 GND (power), B2 GND (power), B5 GND (power), B8 GND (power), B9 GND (power), C5 VCC_6_TEST (power), C11 GND (power), D1 GND (power), D5 GND (power), D8 GND (power), E2 GND (power), H2 GND (power), H4 GND (power), L2 GND (power), L4 GND (power), P2 GND (power), P4 GND (power), R1 GND (power), U2 GND (power), U4 GND (power), V1 GND (power), W3 GND (power), Y2 GND (power), Y3 VCC_5_TEST (power), Y8 VCC_IN_5V (power), Y9 VCC_IN_5V (power), Y10 VCC_IN_5V (power), Y11 VCC_IN_5V (power)

## R
designator R?, comment DNP 15K
RES, Thick Film, 15K, 1%, 1/16W, SMD, 0402; 01. ASET1 UI1: ------------; 09. Z Lay/FP: RES0402_1005
footprint R0402
footprint RES01005_0402
footprint RES0402_1005
pins: 1, 2
1 alternate drawing of the same symbol

## R_1
designator R?, comment DNP 100K
RES, Thick Film, 100K, 1%, 1/16W, SMD, 0402; 01. ASET1 UI1: ------------; 09. Z Lay/FP: RES0402_1005
footprint R0402
footprint RES01005_0402
footprint RES0402_1005
pins: 1, 2
1 alternate drawing of the same symbol

## R_2
designator R?, comment 10K
10K 1% 1/32W 01005; 01. ASET1 UI1: ------------; 01. Set1/BD#: BD3343; 02. Set1/MF1: Bourns Inc.; 03. Set1/PN1: CR01005-FW-1002GLF; 09. Z Lay/FP: RES0402_1005
footprint R0402
footprint RES01005_0402
footprint RES0402_1005
pins: 1, 2
1 alternate drawing of the same symbol

## R_3
designator R?, comment 0R
0R 1/32W 01005; 01. ASET1 UI1: ------------; 01. Set1/BD#: BD3266; 02. Set1/MF1: Yageo; 03. Set1/PN1: RC0100JR-070RL; 09. Z Lay/FP: RES0402_1005
footprint R0402
footprint RES01005_0402
footprint RES0402_1005
pins: 1, 2
1 alternate drawing of the same symbol

## R_4
designator R?, comment 180K
180K 1% 1/32W 01005; 01. ASET1 UI1: ------------; 01. Set1/BD#: BD3338; 02. Set1/MF1: Panasonic; 03. Set1/PN1: ERJ-XGNF1803Y; 09. Z Lay/FP: RES0402_1005
footprint R0402
footprint RES01005_0402
footprint RES0402_1005
pins: 1, 2
1 alternate drawing of the same symbol

## R_5
designator R?, comment 100K
100K 1% 1/32W 01005; 01. ASET1 UI1: ------------; 01. Set1/BD#: BD3339; 02. Set1/MF1: Yageo; 03. Set1/PN1: RC0100FR-07100KL; 09. Z Lay/FP: RES0402_1005
footprint R0402
footprint RES01005_0402
footprint RES0402_1005
pins: 1, 2
1 alternate drawing of the same symbol

## R_6
designator R?, comment 270K
270K 1% 1/32W 01005; 01. ASET1 UI1: ------------; 01. Set1/BD#: BD3422; 02. Set1/MF1: Panasonic; 03. Set1/PN1: ERJ-XGNF2703Y; 09. Z Lay/FP: RES0402_1005
footprint R0402
footprint RES01005_0402
footprint RES0402_1005
pins: 1, 2
1 alternate drawing of the same symbol

## R_7
designator R?, comment DNP
RES, Thick Film, 10K, 1%, 1/16W, SMD, 0402; 01. ASET1 UI1: ------------; 09. Z Lay/FP: RES0402_1005
footprint R0402
footprint RES01005_0402
footprint RES0402_1005
pins: 1, 2
1 alternate drawing of the same symbol

## R_8
designator R?, comment 11K  (value not drawn)
11K 1% 1/32W 01005; 01. ASET1 UI1: ------------; 01. Set1/BD#: BD3418; 02. Set1/MF1: Yageo; 03. Set1/PN1: RC0100FR-0711KL; 09. Z Lay/FP: RES0402_1005
footprint R0402
footprint RES01005_0402
footprint RES0402_1005
pins: 1, 2
1 alternate drawing of the same symbol

## R_9
designator R?, comment 2.2K
2.2K 1% 1/32W 01005; 01. ASET1 UI1: ------------; 01. Set1/BD#: BD3344; 02. Set1/MF1: Yageo; 03. Set1/PN1: RC0100FR-072K2P; 09. Z Lay/FP: RES0402_1005
footprint R0402
footprint RES01005_0402
footprint RES0402_1005
pins: 1, 2
1 alternate drawing of the same symbol

## R_10
designator R?, comment DNP
RES, Thick Film, 2.2k, 1%, 1/16W, SMD, 0402; 01. ASET1 UI1: ------------; 09. Z Lay/FP: RES0402_1005
footprint R0402
footprint RES01005_0402
footprint RES0402_1005
pins: 1, 2
1 alternate drawing of the same symbol

## R_11
designator R?, comment 1K
1K 1% 1/32W 01005; 01. ASET1 UI1: ------------; 01. Set1/BD#: BD3345; 02. Set1/MF1: Yageo; 03. Set1/PN1: RC0100FR-071KL; 09. Z Lay/FP: RES0402_1005
footprint R0402
footprint RES01005_0402
footprint RES0402_1005
pins: 1, 2
1 alternate drawing of the same symbol

## R_12
designator R?, comment DNP
RES, Thick Film, 10K, 1%, 1/20W, SMD, 0201; 01. ASET1 UI1: ------------; 09. Z Lay/FP: RES0402_1005
footprint R0201
footprint RES01005_0402
footprint RES0402_1005
pins: 1, 2
1 alternate drawing of the same symbol

## R_13
designator R?, comment 33R
33R 1% 1/32W 01005; 01. ASET1 UI1: ------------; 01. Set1/BD#: BD3416; 02. Set1/MF1: Yageo; 03. Set1/PN1: RC0100FR-0733RL; 09. Z Lay/FP: RES0402_1005
footprint R0201
footprint RES01005_0402
footprint RES0402_1005
pins: 1, 2
1 alternate drawing of the same symbol

## R_14
designator R?, comment DNP
RES, Thick Film, 0R, 5%, 1/20W, SMD, 0201; 01. ASET1 UI1: ------------; 09. Z Lay/FP: RES0402_1005
footprint R0201
footprint RES01005_0402
footprint RES0402_1005
pins: 1, 2
1 alternate drawing of the same symbol

## R_15
designator R?, comment 5.6K
5.6K OHM 1% 1/32W 01005; 01. ASET1 UI1: ------------; 01. Set1/BD#: BD3784; 02. Set1/MF1: Yageo; 03. Set1/PN1: RC0100FR-075K6L; 09. Z Lay/FP: RES0402_1005
footprint R0402
footprint RES01005_0402
footprint RES0402_1005
pins: 1, 2
1 alternate drawing of the same symbol

## R_16
designator R?, comment 20K
20K 1% 1/32W 01005; 01. ASET1 UI1: ------------; 01. Set1/BD#: BD3341; 02. Set1/MF1: Yageo; 03. Set1/PN1: RC0100FR-0720KL; 09. Z Lay/FP: RES0402_1005
footprint R0402
footprint RES01005_0402
footprint RES0402_1005
pins: 1, 2
1 alternate drawing of the same symbol

## R_17
designator R?, comment 499R  (value not drawn)
499R 1% 1/32W 01005; 01. ASET1 UI1: ------------; 01. Set1/BD#: BD3421; 02. Set1/MF1: Yageo; 03. Set1/PN1: RC0100FR-07499RL; 09. Z Lay/FP: RES0402_1005
footprint R0402
footprint RES01005_0402
footprint RES0402_1005
pins: 1, 2
1 alternate drawing of the same symbol

## R_18
designator R?, comment DNP
01. ASET1 UI1: ------------; 09. Z Lay/FP: RES0402_1005
footprint RES0603_0201
footprint RES01005_0402
footprint RES0402_1005
pins: 1, 2

## R_19
designator R?, comment 49.9K
49.9K 1% 01005; 01. ASET1 UI1: ------------; 01. Set1/BD#: BD3719; 02. Set1/MF1: Vishay Dale; 03. Set1/PN1: CRCW010049K9FREL; 09. Z Lay/FP: RES0402_1005
footprint RES0603_0201
footprint RES0402_1005
pins: 1, 2

## RES_Dup1
designator R?, comment DNP
01. ASET1 UI1: ------------; 09. Z Lay/FP: RES0402_1005
footprint 0402_CC
footprint RES0603_0201
footprint RES01005_0402
footprint RES0402_1005
pins: 1, 2

## RES_Dup1_1
designator R?, comment 240R
240R 1% 1/32W 01005; 01. ASET1 UI1: ------------; 01. Set1/BD#: BD3420; 02. Set1/MF1: Yageo; 03. Set1/PN1: RC0100FR-07240RL; 09. Z Lay/FP: RES0402_1005
footprint RC0603_OV
footprint RES0603_0201
footprint RES01005_0402
footprint RES0402_1005
pins: 1, 2

## RES_Dup3
designator R?, comment 2.2K
2.2K 1% 1/32W 01005; 01. ASET1 UI1: ------------; 01. Set1/BD#: BD3344; 02. Set1/MF1: Yageo; 03. Set1/PN1: RC0100FR-072K2P; 09. Z Lay/FP: RES0402_1005
footprint RES1608_0603
footprint RES0603_0201
footprint RES01005_0402
footprint RES0402_1005
pins: 1, 2

## RES_Dup3_1
designator R?, comment 10K
10K 1% 1/32W 01005; 01. ASET1 UI1: ------------; 01. Set1/BD#: BD3343; 02. Set1/MF1: Bourns Inc.; 03. Set1/PN1: CR01005-FW-1002GLF; 09. Z Lay/FP: RES0402_1005
footprint RC0603_OV
footprint RES1608_0603
footprint RES0402_1005
pins: 1, 2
